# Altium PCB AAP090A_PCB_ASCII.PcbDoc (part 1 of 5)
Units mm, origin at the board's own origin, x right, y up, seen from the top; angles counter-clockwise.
Board outline 160 x 130 mm, 4 copper layers (Top Layer, Signal Layer 1, Signal Layer 2, Bottom Layer), stack 1.567 mm thick; 507 components, 275 nets, 1462 pads, 1041 vias.
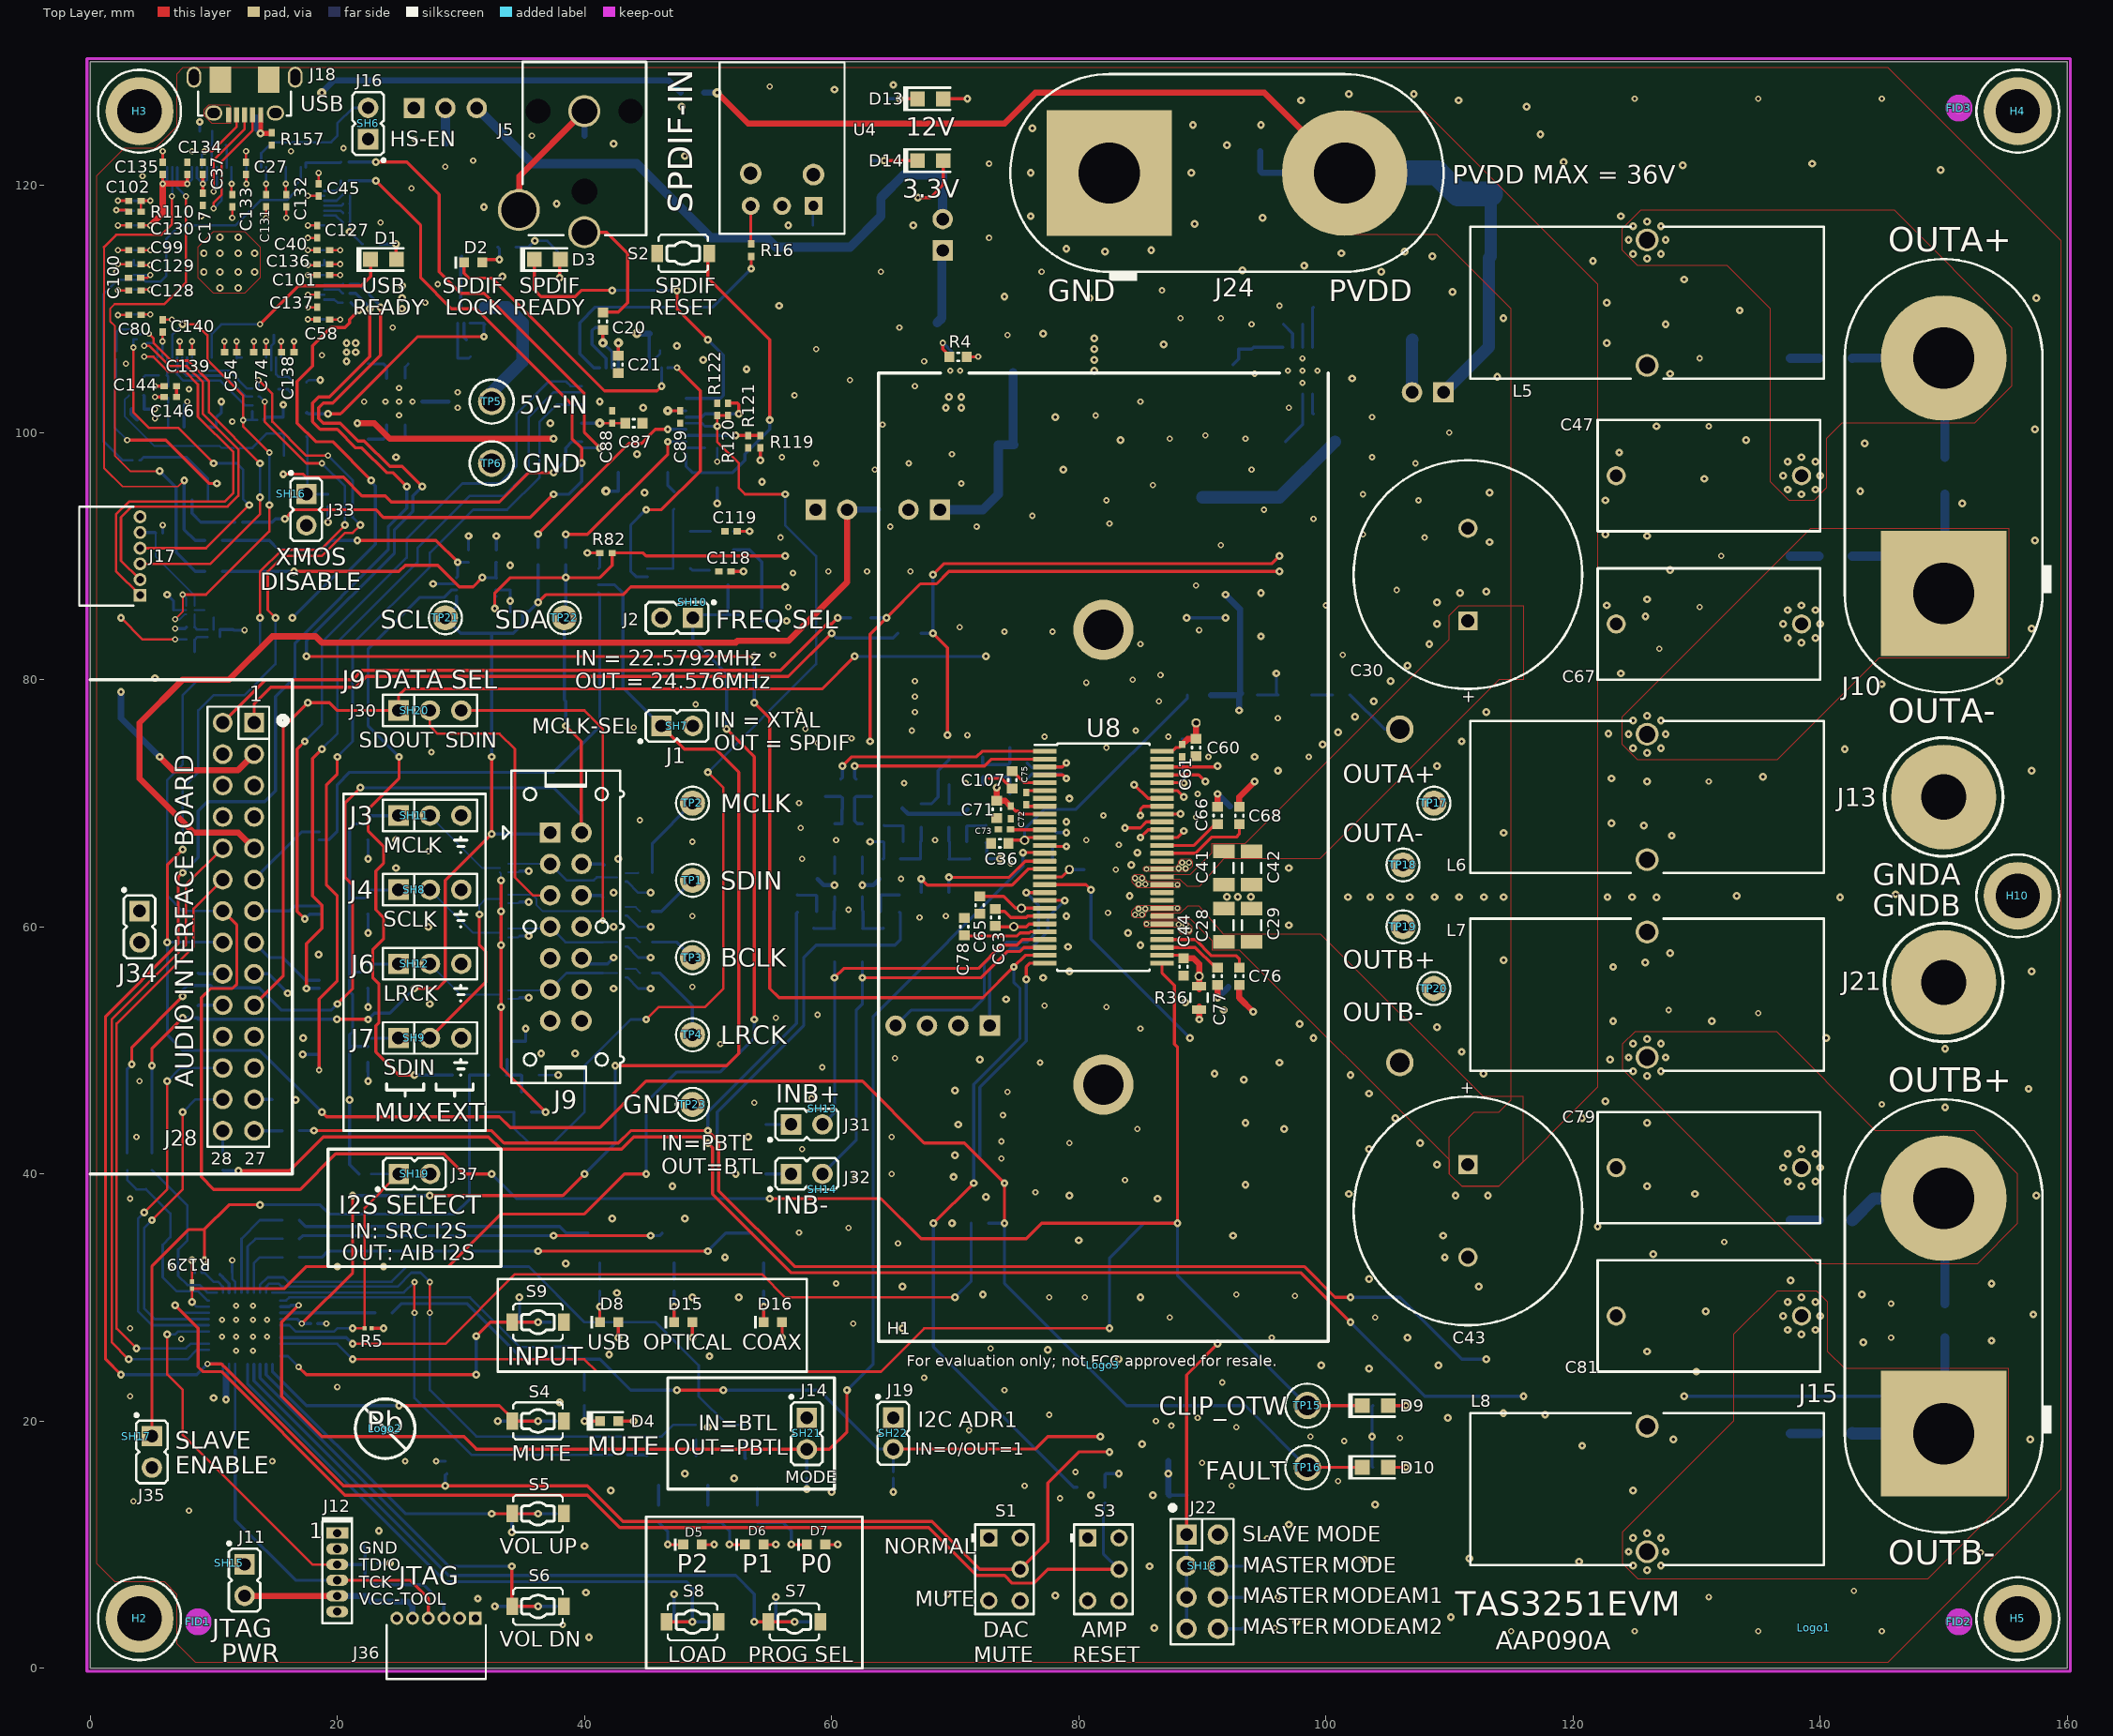
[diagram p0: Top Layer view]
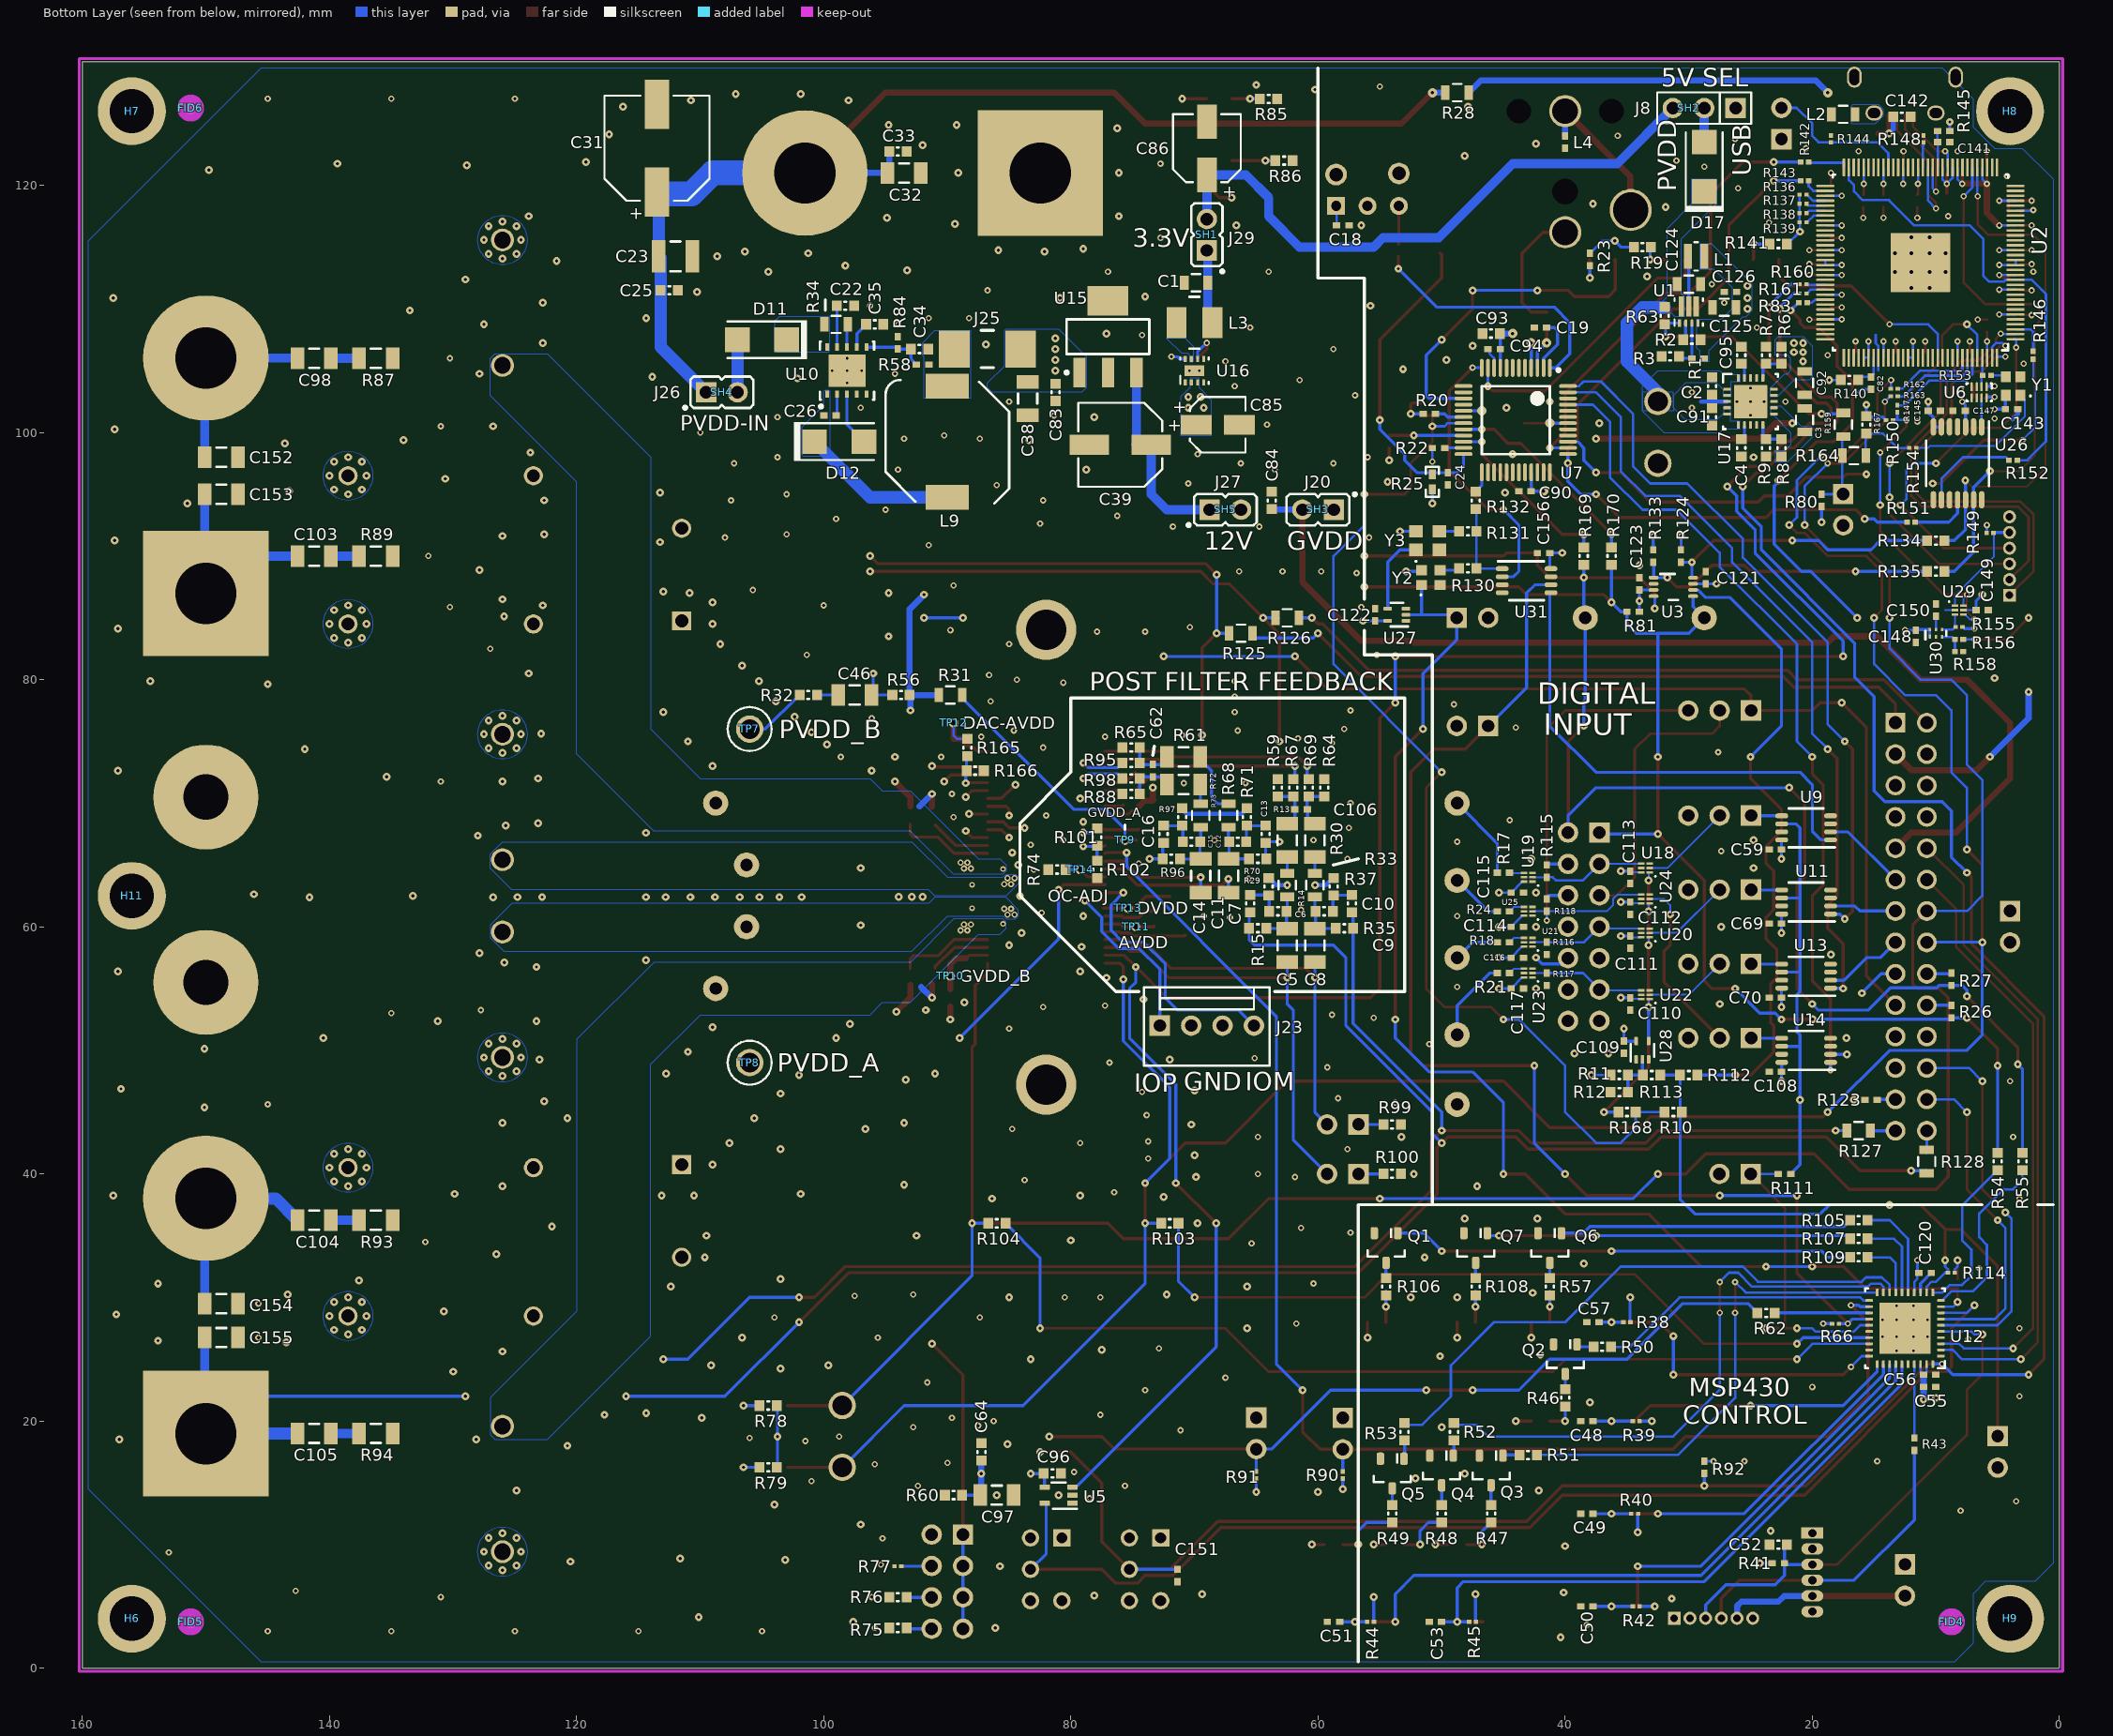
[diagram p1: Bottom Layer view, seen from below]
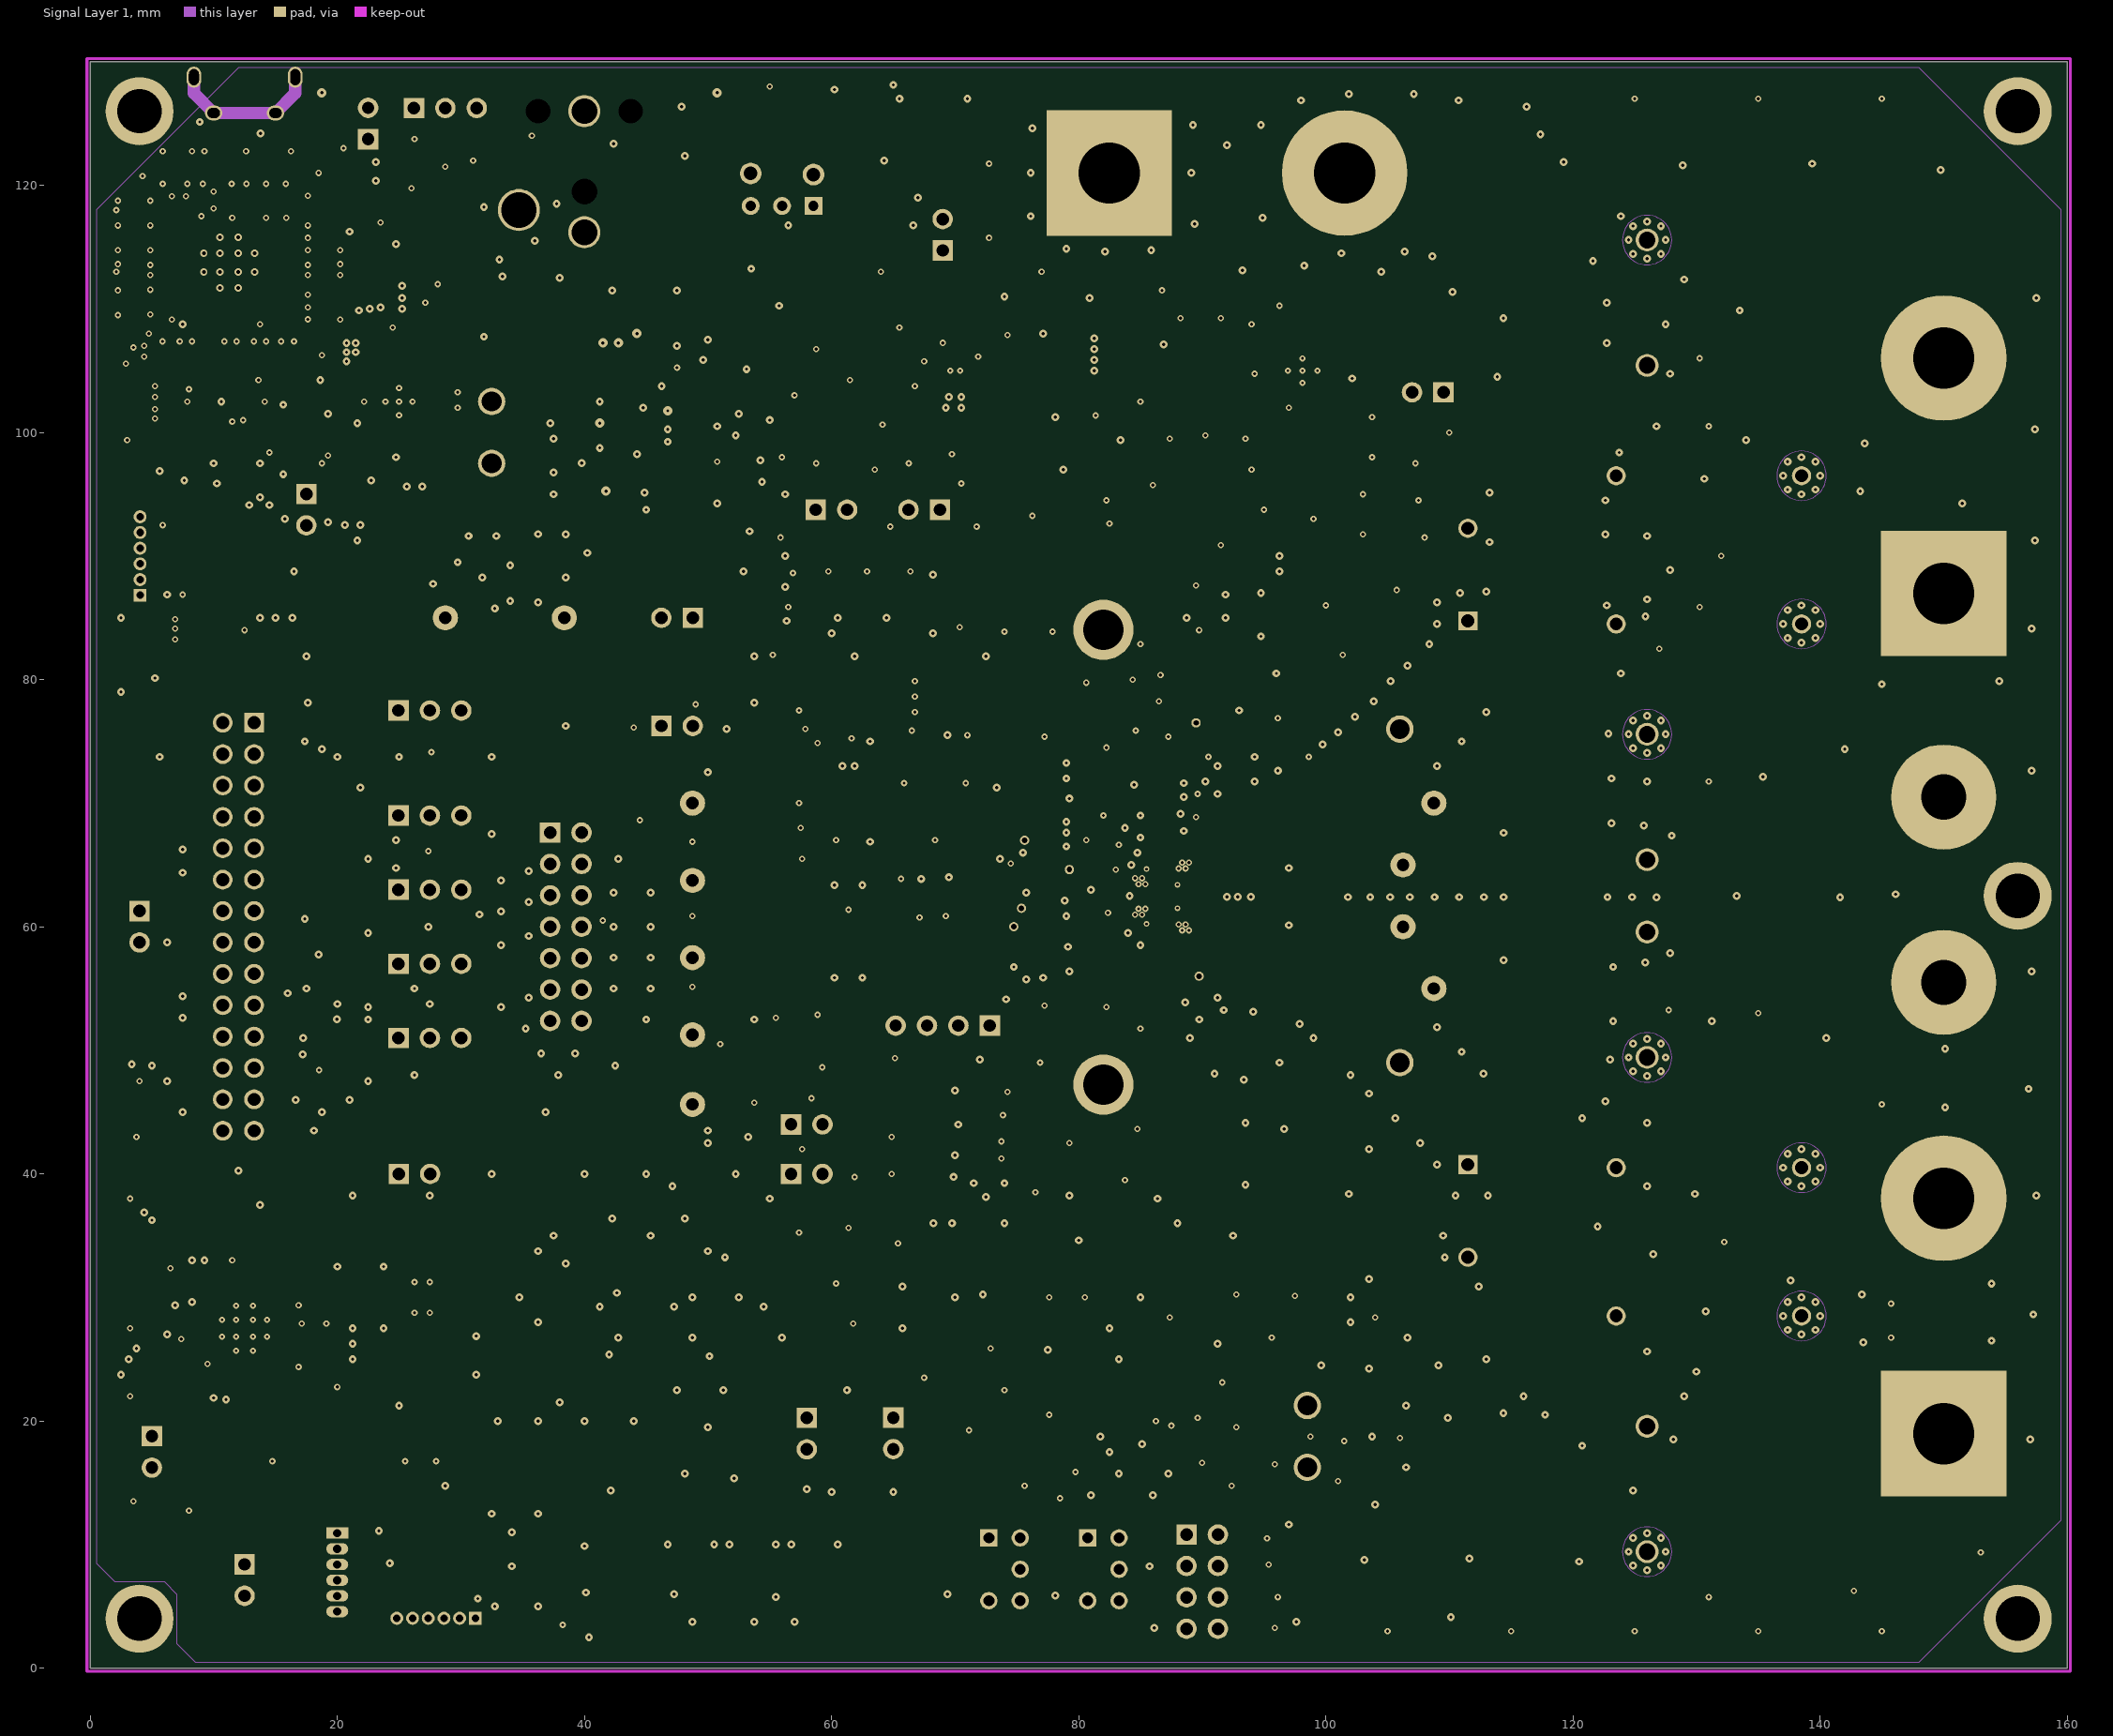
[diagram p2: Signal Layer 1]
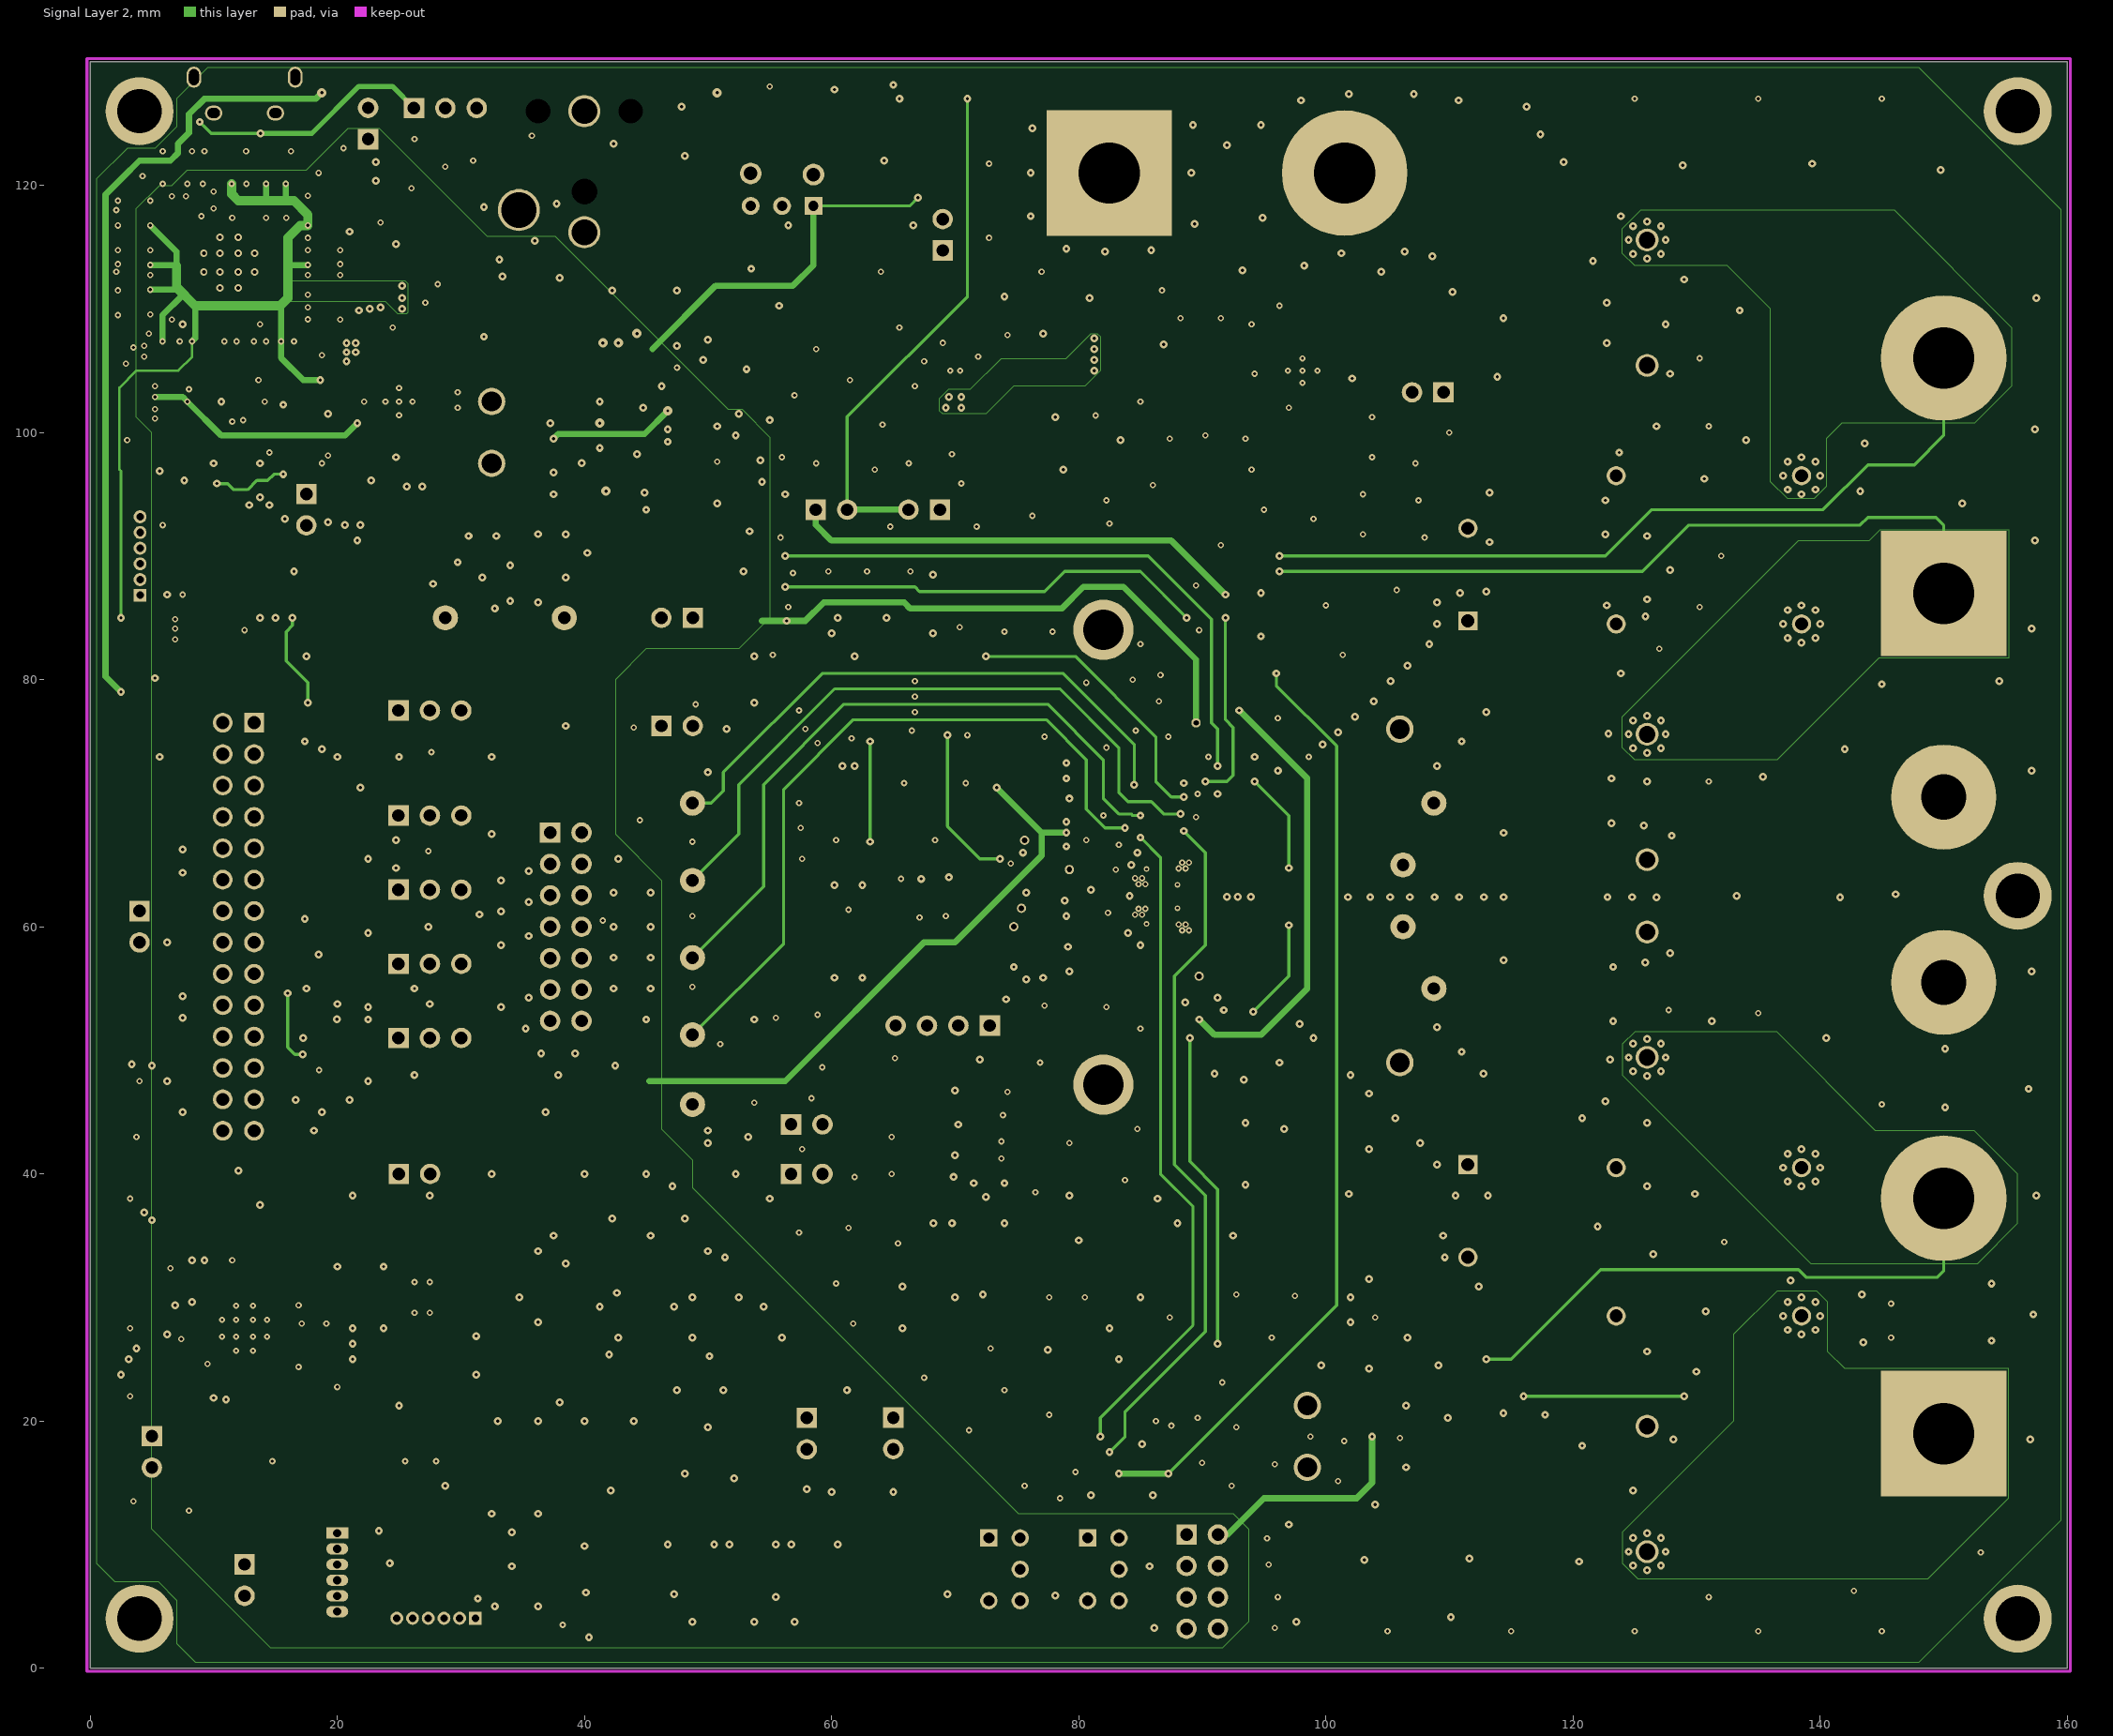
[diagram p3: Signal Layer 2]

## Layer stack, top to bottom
Top Solder: solder mask 0.0102, Solder Resist, Dk 3.5
Top Layer: signal copper 0.0696
Dielectric 1: prepreg 0.2032, FR-4, Dk 4.2
Signal Layer 1: signal copper 0.0356
Dielectric 2: core 0.9505, FR-4, Dk 4.2
Signal Layer 2: signal copper 0.0356
Dielectric 3: prepreg 0.2032, FR-4, Dk 4.2
Bottom Layer: signal copper 0.0696
Bottom Solder: solder mask 0.0102, Solder Resist, Dk 3.5

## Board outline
0,0 160,0 160,130 0,130

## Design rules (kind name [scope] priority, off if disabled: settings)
AcuteAngle [All] p0: scope1count=1 scope1_0_kind=Board scope1_0_value=Board scope2count=1 scope2_0_kind=Board scope2_0_value=Board commentlength=0 minimum=4.50000000000000E+0001
AcuteAngle [All] p1: minimum=4.50000000000000E+0001 checktracksonly=FALSE
AssemblyTestPointUsage [All] p0: scope1count=1 scope1_0_kind=Board scope1_0_value=Board scope2count=1 scope2_0_kind=Board scope2_0_value=Board commentlength=0
AssemblyTestPointUsage [All] p1: valid=2
AssemblyTestpoint [All] p0: scope1count=1 scope1_0_kind=Board scope1_0_value=Board scope2count=1 scope2_0_kind=Board scope2_0_value=Board commentlength=0
BoardOutlineClearance "BOC For Jacks at Edge" [All] p0: scope1count=1 scope1_0_kind=Component scope1_0_value=J18 scope2count=1 scope2_0_kind=Board scope2_0_value=Board commentlength=0 gap=0
BoardOutlineClearance [All] p0 off: scope1count=1 scope1_0_kind=Board scope1_0_value=Board scope2count=1 scope2_0_kind=Board scope2_0_value=Board commentlength=172 gap=0.5 // Protel DXP Scope 1 Expression Was: OnCopper and Not InComponentClass('Logo') and not InComponentClass('FiducialMark') and not InRegion(1000,500,4000,800) and not InPoly
BoardOutlineClearance BoardOutlineClearance_Poly [All] p0 off: scope1count=1 scope1_0_kind=Board scope1_0_value=Board scope2count=1 scope2_0_kind=Board scope2_0_value=Board commentlength=58 gap=0.5 // Protel DXP Scope 1 Expression Was: OnCopper and IsPoly
BoardOutlineClearance BoardOutlineClearance_MountingHoles [All] p0 off: scope1count=1 scope1_0_kind=Board scope1_0_value=Board scope2count=1 scope2_0_kind=Board scope2_0_value=Board commentlength=86 gap=0.25 // Protel DXP Scope 1 Expression Was: OnCopper and InComponentClass('Mounting Holes')
BoardOutlineClearance "BOC For Jacks at Edge" [InComponent('J18')] p1: gap=0 ignorepadtopadclearanceinfootprint=FALSE
BoardOutlineClearance BoardOutlineClearance_MountingHoles [OnCopper and InComponentClass('Mounting Holes')] p2: gap=0.25 ignorepadtopadclearanceinfootprint=FALSE
BoardOutlineClearance BoardOutlineClearance_Poly [OnCopper and IsPoly] p3: gap=0.5 ignorepadtopadclearanceinfootprint=FALSE
BoardOutlineClearance [OnCopper and Not InComponentClass('Logo') and not InComponentClass('FiducialMark') and not InRegion(1000,500,4000,800) and not InPoly] p4: gap=0.5 ignorepadtopadclearanceinfootprint=FALSE
Clearance [All] p0: scope1count=1 scope1_0_kind=Board scope1_0_value=Board scope2count=1 scope2_0_kind=Board scope2_0_value=Board commentlength=0 gap=0.2
Clearance Clearance_Poly [All] p0 off: scope1count=1 scope1_0_kind=Board scope1_0_value=Board scope2count=1 scope2_0_kind=Board scope2_0_value=Board commentlength=48 gap=0.2 // Protel DXP Scope 1 Expression Was: InPolygon
Clearance Clearance_Keepouts [All] p0 off: scope1count=1 scope1_0_kind=Board scope1_0_value=Board scope2count=1 scope2_0_kind=Board scope2_0_value=Board commentlength=99 gap=0 // Protel DXP Scope 2 Expression Was: ((IsTrack Or IsArc) And Not InPoly) And IsFree and IsKeepOut
Clearance "Clearance LibErrors" [All] p0 off: scope1count=1 scope1_0_kind=Board scope1_0_value=Board scope2count=1 scope2_0_kind=Board scope2_0_value=Board commentlength=83 gap=0.2 // Protel DXP Scope 1 Expression Was: HasFootprint('DSF*') or HasFootprint('RLT*')
Clearance "Fiducial Rules Error" [All] p0: scope1count=1 scope1_0_kind=Component scope1_0_value=FID* scope2count=1 scope2_0_kind=Board scope2_0_value=Board commentlength=0 gap=0.2
Clearance "Fiducial Rules Error" [InComponent('FID*')] p1: gap=0.2 ignorepadtopadclearanceinfootprint=TRUE except(0: Arc-SMDPad Arc-Hole Track-SMDPad Track-Hole SMDPad-Hole THPad-Hole Via-Hole Fill-Hole Poly-Hole Region-Hole Text-Hole)
Clearance "Clearance LibErrors" [HasFootprint('DSF*') or HasFootprint('RLT*')] p2: gap=0.2 ignorepadtopadclearanceinfootprint=FALSE except(0: Arc-Hole Track-Hole SMDPad-Hole THPad-Hole Via-Hole Fill-Hole Poly-Hole Region-Hole Text-Hole; 0.1: Track-SMDPad SMDPad-SMDPad)
Clearance Clearance_Keepouts [((IsTrack Or IsArc) And Not InPoly) And IsFree and IsKeepOut vs ((IsTrack Or IsArc) And Not InPoly) And IsFree and IsKeepOut] p3: gap=0 ignorepadtopadclearanceinfootprint=FALSE
Clearance Clearance_Poly [InPolygon] p4: gap=0.2 ignorepadtopadclearanceinfootprint=TRUE except(0: Arc-Hole Track-Hole SMDPad-Hole THPad-Hole Via-Hole Fill-Hole Poly-Hole Region-Hole Text-Hole)
Clearance [All] p5: gap=0.2 ignorepadtopadclearanceinfootprint=FALSE except(0: Arc-Hole Track-Hole SMDPad-Hole THPad-Hole Via-Hole Fill-Hole Poly-Hole Region-Hole Text-Hole)
ComponentClearance "CompClearance for Heatsink" [All] p0: scope1count=1 scope1_0_kind=Component scope1_0_value=H1 scope2count=1 scope2_0_kind=Board scope2_0_value=Board commentlength=0 gap=0 collisioncheckmode=3
ComponentClearance [All] p0: scope1count=1 scope1_0_kind=Board scope1_0_value=Board scope2count=1 scope2_0_kind=Board scope2_0_value=Board commentlength=0 gap=0.25 collisioncheckmode=3
ComponentClearance ComponentClearance_THtoTH [All] p0 off: scope1count=1 scope1_0_kind=Board scope1_0_value=Board scope2count=1 scope2_0_kind=Board scope2_0_value=Board commentlength=54 gap=0.25 collisioncheckmode=3 // Protel DXP Scope 2 Expression Was: IsThruComponent
ComponentClearance ComponentClearance_THtoSMT [All] p0 off: scope1count=1 scope1_0_kind=Board scope1_0_value=Board scope2count=1 scope2_0_kind=Board scope2_0_value=Board commentlength=53 gap=0.25 collisioncheckmode=3 // Protel DXP Scope 2 Expression Was: IsSMTComponent
ComponentClearance ComponentClearance_SmallPassives [All] p0 off: scope1count=1 scope1_0_kind=Board scope1_0_value=Board scope2count=1 scope2_0_kind=Board scope2_0_value=Board commentlength=653 gap=0.25 collisioncheckmode=3 // Protel DXP Scope 2 Expression Was: HasFootprint('0201*') or HasFootprint('0402*') or HasFootprint('0508') or HasFootprint('0603*') or HasFootprint('0612') or HasFootprint('0805*') or HasFootprint('0815*') or HasFootprint('0830*') or HasFootprint('1206*') or HasFootprint('1210*') or HasFootprint('1808*') or HasFootprint('1812*') or HasFootprint('1825*') or HasFootprint('2010*') or HasFootprint('2220*') or HasFootprint('2225*') or HasFootprint('2512*') or HasFootprint('2728*') or HasFootprint('3518*') or HasFootprint('DKQ*') or HasFootprint('OSC*') or HasFootprint('PFB*') or HasFootprint('RHB*') or HasFootprint('SOT*') or HasFootprint('XTAL*')
ComponentClearance ComponentClearance_MountingHoles [All] p0: scope1count=1 scope1_0_kind=ComponentClass scope1_0_value="Mounting Holes" scope2count=1 scope2_0_kind=Board scope2_0_value=Board commentlength=0 gap=0 collisioncheckmode=3
ComponentClearance ComponentClearance_Logo [All] p0: scope1count=1 scope1_0_kind=ComponentClass scope1_0_value=Logo scope2count=1 scope2_0_kind=Board scope2_0_value=Board commentlength=0 gap=0 collisioncheckmode=3
ComponentClearance ComponentClearance_Shunt [All] p0: scope1count=1 scope1_0_kind=ComponentClass scope1_0_value=Header scope2count=1 scope2_0_kind=ComponentClass scope2_0_value=Shunt commentlength=0 gap=0 collisioncheckmode=3
ComponentClearance ComponentClearance_MountingHoles_FiducialMarks [All] p0: scope1count=1 scope1_0_kind=ComponentClass scope1_0_value="Mounting Holes" scope2count=1 scope2_0_kind=ComponentClass scope2_0_value=FiducialMark commentlength=0 gap=0.25 collisioncheckmode=3
ComponentClearance "CompClearance for Heatsink" [InComponent('H1')] p1: gap=0 collisioncheckmode=3 verticalgap=0 showdistances=FALSE
ComponentClearance ComponentClearance_MountingHoles_FiducialMarks [InComponentClass('Mounting Holes') vs InComponentClass('FiducialMark')] p2: gap=0.25 collisioncheckmode=3 verticalgap=0 showdistances=FALSE
ComponentClearance ComponentClearance_Shunt [InComponentClass('Header') vs InComponentClass('Shunt')] p3: gap=0 collisioncheckmode=3 verticalgap=0 showdistances=FALSE
ComponentClearance ComponentClearance_Logo [InComponentClass('Logo')] p4: gap=0 collisioncheckmode=3 verticalgap=0 showdistances=FALSE
ComponentClearance ComponentClearance_MountingHoles [InComponentClass('Mounting Holes')] p5: gap=0 collisioncheckmode=3 verticalgap=0 showdistances=FALSE
ComponentClearance ComponentClearance_SmallPassives [HasFootprint('0201*') or HasFootprint('0402*') or HasFootprint('0508') or HasFootprint('0603*') or HasFootprint('0612') or HasFootprint('0805*') or HasFootprint('0815*') or HasFootprint('0830*') or HasFootprint('1206*') or HasFootprint('1210*') or HasFootprint('1808*') or HasFootprint('1812*') or HasFootprint('1825*') or HasFootprint('2010*') or HasFootprint('2220*') or HasFootprint('2225*') or HasFootprint('2512*') or HasFootprint('2728*') or HasFootprint('3518*') or HasFootprint('DKQ*') or HasFootprint('OSC*') or HasFootprint('PFB*') or HasFootprint('RHB*') or HasFootprint('SOT*') or HasFootprint('XTAL*') vs HasFootprint('0201*') or HasFootprint('0402*') or HasFootprint('0508') or HasFootprint('0603*') or HasFootprint('0612') or HasFootprint('0805*') or HasFootprint('0815*') or HasFootprint('0830*') or HasFootprint('1206*') or HasFootprint('1210*') or HasFootprint('1808*') or HasFootprint('1812*') or HasFootprint('1825*') or HasFootprint('2010*') or HasFootprint('2220*') or HasFootprint('2225*') or HasFootprint('2512*') or HasFootprint('2728*') or HasFootprint('3518*') or HasFootprint('DKQ*') or HasFootprint('OSC*') or HasFootprint('PFB*') or HasFootprint('RHB*') or HasFootprint('SOT*') or HasFootprint('XTAL*')] p6: gap=0.25 collisioncheckmode=3 verticalgap=0 showdistances=FALSE
ComponentClearance ComponentClearance_THtoSMT [IsThruComponent vs IsSMTComponent] p7: gap=0.25 collisioncheckmode=3 verticalgap=0 showdistances=FALSE
ComponentClearance ComponentClearance_THtoTH [IsThruComponent vs IsThruComponent] p8: gap=0.25 collisioncheckmode=3 verticalgap=0 showdistances=FALSE
ComponentClearance [All] p9: gap=0.25 collisioncheckmode=3 verticalgap=0 showdistances=FALSE
DiffPairsRouting [All] p0: scope1count=1 scope1_0_kind=Board scope1_0_value=Board scope2count=1 scope2_0_kind=Board scope2_0_value=Board commentlength=0
DiffPairsRouting [All] p1: maxlimit=2.54 minlimit=0.254 mostfreqgap=0.254 toplayer_minwidth=0.381 toplayer_maxwidth=0.381 toplayer_prefwidth=0.381 midlayer1_minwidth=0.381 midlayer1_maxwidth=0.381 midlayer1_prefwidth=0.381 midlayer2_minwidth=0.381 midlayer2_maxwidth=0.381 midlayer2_prefwidth=0.381 bottomlayer_minwidth=0.381 bottomlayer_maxwidth=0.381 bottomlayer_prefwidth=0.381 maxuncoupledlength=25.4
FabricationTestPointUsage TestPointUsage [All] p0: scope1count=1 scope1_0_kind=Board scope1_0_value=Board scope2count=1 scope2_0_kind=Board scope2_0_value=Board commentlength=0 valid=2 allowmultiple=FALSE
FabricationTestPointUsage TestPointUsage [All] p1: valid=2 allowmultiple=FALSE
FabricationTestpoint Testpoint [All] p0: scope1count=1 scope1_0_kind=Board scope1_0_value=Board scope2count=1 scope2_0_kind=Board scope2_0_value=Board commentlength=0 side=3 testpointundercomponent=TRUE minsize=1.016 maxsize=2.54 preferedsize=1.524 minholesize=0 maxholesize=1.016 preferedholesize=0.813 testpointgrid=0.025
FabricationTestpoint Testpoint [All] p1: side=3 testpointundercomponent=TRUE minsize=1.016 maxsize=2.54 preferedsize=1.524 minholesize=0 maxholesize=1.016 preferedholesize=0.813 testpointgrid=0.025 allowsidetop=TRUE allowsidebottom=TRUE usegrid=TRUE gridtolerance=0
FanoutControl Fanout_Small [All] p0 off: scope1count=1 scope1_0_kind=Board scope1_0_value=Board scope2count=1 scope2_0_kind=Board scope2_0_value=Board commentlength=84 // Protel DXP Scope 1 Expression Was: (CompPinCount < 5)   Fanout_Small (Default Rule)
FanoutControl Fanout_Default [All] p0: scope1count=1 scope1_0_kind=Board scope1_0_value=Board scope2count=1 scope2_0_kind=Board scope2_0_value=Board commentlength=30 // Fanout_Default (Default Rule)
FanoutControl Fanout_SOIC [All] p0 off: scope1count=1 scope1_0_kind=Board scope1_0_value=Board scope2count=1 scope2_0_kind=Board scope2_0_value=Board commentlength=71 // Protel DXP Scope 1 Expression Was: IsSOIC   Fanout_SOIC (Default Rule)
FanoutControl Fanout_BGA [All] p0 off: scope1count=1 scope1_0_kind=Board scope1_0_value=Board scope2count=1 scope2_0_kind=Board scope2_0_value=Board commentlength=69 // Protel DXP Scope 1 Expression Was: IsBGA   Fanout_BGA (Default Rule)
FanoutControl Fanout_LCC [All] p0 off: scope1count=1 scope1_0_kind=Board scope1_0_value=Board scope2count=1 scope2_0_kind=Board scope2_0_value=Board commentlength=69 // Protel DXP Scope 1 Expression Was: IsLCC   Fanout_LCC (Default Rule)
FanoutControl Fanout_LCC [IsLCC] p1: bgadir=Out bgaviamode=Centered fanoutstyle=Auto fanoutdirection=Alternating viagrid=0.025 // Fanout_LCC (Default Rule)
FanoutControl Fanout_BGA [IsBGA] p2: bgadir=Out bgaviamode=Centered fanoutstyle=Auto fanoutdirection=Alternating viagrid=0.025 // Fanout_BGA (Default Rule)
FanoutControl Fanout_Default [All] p4: bgadir=Out bgaviamode=Centered fanoutstyle=Auto fanoutdirection=Alternating viagrid=0.025 // Fanout_Default (Default Rule)
FanoutControl Fanout_Small [(CompPinCount < 5)] p5: bgadir=Out bgaviamode=Centered fanoutstyle=Auto fanoutdirection=OutThenIn viagrid=0.025 // Fanout_Small (Default Rule)
Height [All] p0: scope1count=1 scope1_0_kind=Board scope1_0_value=Board scope2count=1 scope2_0_kind=Board scope2_0_value=Board commentlength=0
Height [All] p1: minheight=0 maxheight=38.1 prefheight=12.7
HoleSize [All] p0: scope1count=1 scope1_0_kind=Board scope1_0_value=Board scope2count=1 scope2_0_kind=Board scope2_0_value=Board commentlength=0 absolutevalues=TRUE maxlimit=6.375 minlimit=0.2 maxpercent=80.000 minpercent=20.000
HoleSize [All] p1: absolutevalues=TRUE maxlimit=6.375 minlimit=0.2 maxpercent=80.000 minpercent=20.000
HoleToHoleClearance [All] p0: scope1count=1 scope1_0_kind=Board scope1_0_value=Board scope2count=1 scope2_0_kind=Board scope2_0_value=Board commentlength=0
LayerPairs [All] p0: scope1count=1 scope1_0_kind=Board scope1_0_value=Board scope2count=1 scope2_0_kind=Board scope2_0_value=Board commentlength=0 enforce=TRUE
MinimumAnnularRing [All] p0: scope1count=1 scope1_0_kind=Board scope1_0_value=Board scope2count=1 scope2_0_kind=Board scope2_0_value=Board commentlength=0 minimumring=0.127
MinimumAnnularRing MinimumAnnularRing_ThermalPadVias [All] p0 off: scope1count=1 scope1_0_kind=Board scope1_0_value=Board scope2count=1 scope2_0_kind=Board scope2_0_value=Board commentlength=63 minimumring=0.15 // Protel DXP Scope 1 Expression Was: IsVia and InAnyComponent
MinimumAnnularRing MinimumAnnularRing_ThermalPadVias [IsVia and InAnyComponent] p1: minimumring=0.15
MinimumAnnularRing [All] p2: minimumring=0.127
MinimumSolderMaskSliver "MinSolderMaskSliver LibErrors" [All] p0 off: scope1count=1 scope1_0_kind=Board scope1_0_value=Board scope2count=1 scope2_0_kind=Board scope2_0_value=Board commentlength=203 // Protel DXP Scope 1 Expression Was: HasFootprint('DCU*') or HasFootprint('DQM*') or HasFootprint('DRL*') or HasFootprint('DSF*') or HasFootprint('PFB*') or HasFootprint('PW*') or HasFootprint('TQFP*')
MinimumSolderMaskSliver [All] p0: scope1count=1 scope1_0_kind=Board scope1_0_value=Board scope2count=1 scope2_0_kind=Board scope2_0_value=Board commentlength=0
MinimumSolderMaskSliver MinimumSolderMaskSliver_Logo [All] p0: scope1count=1 scope1_0_kind=ComponentClass scope1_0_value=Logo scope2count=1 scope2_0_kind=ComponentClass scope2_0_value=Logo commentlength=0
MinimumSolderMaskSliver "MinSolderMaskSliver LibErrors" [HasFootprint('DCU*') or HasFootprint('DQM*') or HasFootprint('DRL*') or HasFootprint('DSF*') or HasFootprint('PFB*') or HasFootprint('PW*') or HasFootprint('TQFP*')] p1: minsoldermaskwidth=0.064
MinimumSolderMaskSliver MinimumSolderMaskSliver_Logo [InComponentClass('Logo') vs InComponentClass('Logo')] p2: minsoldermaskwidth=0.018
MinimumSolderMaskSliver [All] p3: minsoldermaskwidth=0.102
NetAntennae [All] p0: scope1count=1 scope1_0_kind=Board scope1_0_value=Board scope2count=1 scope2_0_kind=Board scope2_0_value=Board commentlength=0
PasteMaskExpansion [All] p0: scope1count=1 scope1_0_kind=Board scope1_0_value=Board scope2count=1 scope2_0_kind=Board scope2_0_value=Board commentlength=0 expansion=0
PlaneClearance [All] p0: scope1count=1 scope1_0_kind=Board scope1_0_value=Board scope2count=1 scope2_0_kind=Board scope2_0_value=Board commentlength=0 clearance=0.508
PlaneConnect [All] p0: scope1count=1 scope1_0_kind=Board scope1_0_value=Board scope2count=1 scope2_0_kind=Board scope2_0_value=Board commentlength=0 planeconnectstyle=Relief reliefexpansion=0.254 reliefentries=4 reliefconductorwidth=0.254 reliefairgap=0.254
PlaneConnect [All] p1: planeconnectstyle=Relief reliefexpansion=0.254 reliefentries=4 reliefconductorwidth=0.254 reliefairgap=0.254
PolygonConnect "GND Thermals 0.5mm" [All] p0 off: scope1count=1 scope1_0_kind=Board scope1_0_value=Board scope2count=1 scope2_0_kind=Net scope2_0_value=GND commentlength=416 connectstyle=Relief reliefconductorwidth=0.5 reliefentries=4 polygonreliefangle="90 Angle" // Protel DXP Scope 1 Expression Was: InComponent('C23') or InComponent('C30') or  InComponent('C32') or InComponent('C39') or  InComponent('C43') or InComponent('C47') or  InComponent('C67') or InComponent('C79') or  InComponent('C81') or InComponent('C85') or  InComponent('C86') or InComponent('L2') or  InComponent('R87') or InComponent('R89') or  InComponent('R93') or InComponent('R94') or  InComponent('U16')
PolygonConnect "PostFlood GND" [All] p0 off: scope1count=1 scope1_0_kind=Board scope1_0_value=Board scope2count=1 scope2_0_kind=Net scope2_0_value=GND commentlength=595 connectstyle=Direct reliefconductorwidth=0.254 reliefentries=4 polygonreliefangle="90 Angle" // Protel DXP Scope 1 Expression Was: InComponent('C16') or InComponent('C28') or InComponent('C29') or  InComponent('C31') or InComponent('C41') or InComponent('C42') or  InComponent('C44') or InComponent('C55') or InComponent('C56') or  InComponent('C60') or InComponent('C61') or InComponent('C63') or  InComponent('C65') or InComponent('C71') or InComponent('C72') or  InComponent('C73') or InComponent('C78') or InComponent('C124') or  InComponent('C125') or InComponent('C126')  or InComponent('J13') or InComponent('J21') or InComponent('J24') or InComponent('R74') or  InComponent('U1')
PolygonConnect "GND Thermals 0.25mm" [All] p0 off: scope1count=1 scope1_0_kind=Board scope1_0_value=Board scope2count=1 scope2_0_kind=Net scope2_0_value=GND commentlength=203 connectstyle=Relief reliefconductorwidth=0.25 reliefentries=4 polygonreliefangle="90 Angle" // Protel DXP Scope 1 Expression Was: InComponent('C*') or InComponent('D*') or InComponent('J*') or InComponent('Q*') or InComponent('R*') or InComponent('S*') or InComponent('U1') or InComponent('U4')
PolygonConnect PreFlood [All] p0: scope1count=1 scope1_0_kind=Board scope1_0_value=Board scope2count=1 scope2_0_kind=Board scope2_0_value=Board commentlength=0 connectstyle=Direct reliefconductorwidth=0.254 reliefentries=4 polygonreliefangle="90 Angle"
PolygonConnect "PostFlood GND" [InComponent('C16') or InComponent('C28') or InComponent('C29') or  InComponent('C31') or InComponent('C41') or InComponent('C42') or  InComponent('C44') or InComponent('C55') or InComponent('C56') or  InComponent('C60') or InComponent('C61') or InComponent('C63') or  InComponent('C65') or InComponent('C71') or InComponent('C72') or  InComponent('C73') or InComponent('C78') or InComponent('C124') or  InComponent('C125') or InComponent('C126')  or InComponent('J13') or InComponent('J21') or InComponent('J24') or InComponent('R74') or  InComponent('U1') vs InNet('GND')] p1: connectstyle=Direct reliefconductorwidth=0.254 reliefentries=4 polygonreliefangle="90 Angle" airgapwidth=0.254
PolygonConnect "GND Thermals 0.5mm" [InComponent('C23') or InComponent('C30') or  InComponent('C32') or InComponent('C39') or  InComponent('C43') or InComponent('C47') or  InComponent('C67') or InComponent('C79') or  InComponent('C81') or InComponent('C85') or  InComponent('C86') or InComponent('L2') or  InComponent('R87') or InComponent('R89') or  InComponent('R93') or InComponent('R94') or  InComponent('U16') vs InNet('GND')] p2: connectstyle=Relief reliefconductorwidth=0.5 reliefentries=4 polygonreliefangle="90 Angle" airgapwidth=0.2
PolygonConnect "GND Thermals 0.25mm" [InComponent('C*') or InComponent('D*') or InComponent('J*') or InComponent('Q*') or InComponent('R*') or InComponent('S*') or InComponent('U1') or InComponent('U4') vs InNet('GND')] p3: connectstyle=Relief reliefconductorwidth=0.25 reliefentries=4 polygonreliefangle="90 Angle" airgapwidth=0.2
PolygonConnect PreFlood [All] p4: connectstyle=Direct reliefconductorwidth=0.254 reliefentries=4 polygonreliefangle="90 Angle" airgapwidth=0.254
RoutingCorners [All] p0: scope1count=1 scope1_0_kind=Board scope1_0_value=Board scope2count=1 scope2_0_kind=Board scope2_0_value=Board commentlength=0 cornerstyle=45-Degree minsetback=2.54 maxsetback=2.54
RoutingLayers [All] p0: scope1count=1 scope1_0_kind=Board scope1_0_value=Board scope2count=1 scope2_0_kind=Board scope2_0_value=Board commentlength=0 top layer=Automatic mid layer 1=Automatic mid layer 2=Automatic bottom layer=Automatic
RoutingPriority [All] p0: scope1count=1 scope1_0_kind=Board scope1_0_value=Board scope2count=1 scope2_0_kind=Board scope2_0_value=Board commentlength=0
RoutingTopology [All] p0: scope1count=1 scope1_0_kind=Board scope1_0_value=Board scope2count=1 scope2_0_kind=Board scope2_0_value=Board commentlength=0 topology=Shortest
RoutingVias [All] p0: scope1count=1 scope1_0_kind=Board scope1_0_value=Board scope2count=1 scope2_0_kind=Board scope2_0_value=Board commentlength=0 holewidth=0.406 width=0.864 viastyle="Through Hole" minholewidth=0.2 minwidth=0.457 maxholewidth=1.016 maxwidth=1.651
RoutingVias ThermalPadVias [All] p0 off: scope1count=1 scope1_0_kind=Board scope1_0_value=Board scope2count=1 scope2_0_kind=Board scope2_0_value=Board commentlength=63 holewidth=0.2 width=0.5 viastyle="Through Hole" minholewidth=0.2 minwidth=0.5 maxholewidth=0.33 maxwidth=0.6 // Protel DXP Scope 1 Expression Was: IsVia and InAnyComponent
RoutingVias ThermalPadVias [IsVia and InAnyComponent] p1: holewidth=0.2 width=0.5 viastyle="Through Hole" minholewidth=0.2 minwidth=0.5 maxholewidth=0.33 maxwidth=0.6
RoutingVias [All] p2: holewidth=0.406 width=0.864 viastyle="Through Hole" minholewidth=0.2 minwidth=0.457 maxholewidth=1.016 maxwidth=1.651
ShortCircuit [All] p0: scope1count=1 scope1_0_kind=Board scope1_0_value=Board scope2count=1 scope2_0_kind=Board scope2_0_value=Board commentlength=0 allowed=FALSE
SilkToBoardRegionClearance [All] p0 off: scope1count=1 scope1_0_kind=Board scope1_0_value=Board scope2count=1 scope2_0_kind=Board scope2_0_value=Board commentlength=130 // Protel DXP Scope 1 Expression Was: Not ((IsComment or IsDesignator) And (Hide <> 'False')) and not InRegion(1000,500,4000,800)
SilkToBoardRegionClearance [Not ((IsComment or IsDesignator) And (Hide <> 'False')) and not InRegion(1000,500,4000,800)] p1:
SilkToSilkClearance [All] p0: scope1count=1 scope1_0_kind=Board scope1_0_value=Board scope2count=1 scope2_0_kind=Board scope2_0_value=Board commentlength=0
SilkToSilkClearance SilkToSilkClearance_Pb-FreeLogo [All] p0 off: scope1count=1 scope1_0_kind=Board scope1_0_value=Board scope2count=1 scope2_0_kind=Board scope2_0_value=Board commentlength=120 // Protel DXP Scope 2 Expression Was: (HasFootprint('Pb-Free_Overlay_Medium') OR HasFootprint('Pb-Free_Overlay_Small'))
SilkToSilkClearance SilkToSilkClearance_Pb-FreeLogo [(HasFootprint('Pb-Free_Overlay_Medium') OR HasFootprint('Pb-Free_Overlay_Small')) vs (HasFootprint('Pb-Free_Overlay_Medium') OR HasFootprint('Pb-Free_Overlay_Small'))] p1: silktosilkclearance=0
SilkToSilkClearance [All] p2: silktosilkclearance=0.102
SilkToSolderMaskClearance "Silk to Solder Mask Opening" [All] p0: scope1count=1 scope1_0_kind=Board scope1_0_value=Board scope2count=1 scope2_0_kind=Board scope2_0_value=Board commentlength=0
SilkToSolderMaskClearance SilkToComponentPadClearance [All] p0 off: scope1count=1 scope1_0_kind=Board scope1_0_value=Board scope2count=1 scope2_0_kind=Board scope2_0_value=Board commentlength=63 // Protel DXP Scope 1 Expression Was: IsPad and InAnycomponent
SilkToSolderMaskClearance SilkToComponentPadClearance [IsPad and InAnycomponent] p1: minsilkscreentomaskgap=0.127 clearancetoexposedcopper=TRUE
SilkToSolderMaskClearance "Silk to Solder Mask Opening" [All] p2: minsilkscreentomaskgap=0.102 clearancetoexposedcopper=FALSE
SolderMaskExpansion [All] p0: scope1count=1 scope1_0_kind=Board scope1_0_value=Board scope2count=1 scope2_0_kind=Board scope2_0_value=Board commentlength=0 expansion=0.05
SolderMaskExpansion [All] p1: expansion=0.05
UnRoutedNet [All] p0: scope1count=1 scope1_0_kind=Board scope1_0_value=Board scope2count=1 scope2_0_kind=Board scope2_0_value=Board commentlength=0
UnpouredPolygon [All] p0: scope1count=1 scope1_0_kind=Board scope1_0_value=Board scope2count=1 scope2_0_kind=Board scope2_0_value=Board commentlength=0
Width [All] p0: scope1count=1 scope1_0_kind=Board scope1_0_value=Board scope2count=1 scope2_0_kind=Board scope2_0_value=Board commentlength=0 maxlimit=2.54 minlimit=0.15 preferedwidth=0.254
Width [All] p1: maxlimit=2.54 minlimit=0.15 preferedwidth=0.254 toplayer_minwidth=0.152 midlayer1_minwidth=0.152 midlayer2_minwidth=0.152 minimp=50.000000 maximp=50.000000 favimp=50.000000 checkconnectedcopper=TRUE
14 further rules are at their usual default settings.

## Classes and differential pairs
component class "Mounting Holes": H2 H3 H4 H5 H6 H7 H8 H9 H10 H11 H12 H13 H14 H15
component class Header: J1 J2 J3 J4 J6 J7 J8 J11 J14 J16 J19 J20 J22 J26 J27 J29 J30 J31 J32 J33 J34 J35 J37
component class AAP090A_XMOS: C17 C27 C37 C40 C45 C54 C58 C74 C80 C82 C99 C100 C101 C102 C124 C125 C126 C127 C128 C129 C130 C131 C132 C133 C134 C135 C136 C137 C138 C139 C140 C141 C142 C143 C144 C145 C146 C147 C148 C149 C150 D1 J16 J17 J18 J33 L1 L2 R1 R2 R3 R63 R80 R81 R82 R83 R110 R124 R133 R134 R135 R136 R137 R138 R139 R140 R141 R142 R143 R144 R145 R146 R147 R148 R149 R150 R151 R152 R153 R154 R155 R156 R157 R158 R159 R160 R161 R162 R163 R164 R167 U1 U2 U3 U6 U26 U29 U30 Y1
component class AAP090A_TAS3251DKQ-IO: C5 C6 C7 C8 C9 C10 C11 C12 C13 C14 C15 C16 C28 C29 C30 C36 C41 C42 C43 C44 C47 C60 C61 C62 C63 C65 C66 C67 C68 C71 C72 C73 C75 C76 C77 C78 C79 C81 C98 C103 C104 C105 C106 C107 C152 C153 C154 C155 D9 D10 H1 J10 J13 J14 J15 J19 J20 J21 J22 J23 J31 J32 L5 L6 L7 L8 R13 R14 R15 R29 R30 R31 R33 R35 R36 R37 R59 R61 R64 R65 R67 R68 R69 R70 R71 R72 R73 R74 R75 R76 R77 R78 R79 R87 R88 R89 R90 R91 R93 R94 R95 R96 R97 R98 R99 R100 R101 R102 R125 R126 R127 R128 R165 R166 TP1 TP2 TP3 TP4 TP7 TP8 TP9 TP10 TP11 TP12 TP13 TP14 TP15 TP16 TP17 TP18 TP19 TP20 TP21 TP22 TP23 U8
component class AAP090A_SPDIF-SRC4392: C18 C19 C20 C21 C24 C59 C69 C70 C108 C110 C111 C112 C113 C114 C115 C116 C117 C118 C119 C120 C121 C122 C123 C156 D2 D3 J1 J3 J4 J5 J6 J7 J9 J28 J30 J34 L4 R11 R12 R16 R17 R18 R19 R20 R21 R22 R23 R24 R25 R26 R27 R28 R66 R115 R116 R117 R118 R119 R120 R121 R122 R123 R130 R131 R132 R168 R169 R170 S2 U4 U7 U9 U11 U13 U14 U18 U19 U20 U21 U22 U23 U24 U25 U27 U28 U31 Y2 Y3
component class AAP090A_PowerSupplies: C1 C2 C3 C4 C22 C23 C25 C26 C31 C32 C33 C34 C35 C38 C39 C83 C84 C85 C86 C87 C88 C89 C90 C91 C92 C93 C94 C95 D11 D12 D13 D14 D17 J8 J24 J25 J26 J27 J29 L3 L9 R4 R6 R7 R8 R9 R34 R58 R84 R85 R86 TP5 TP6 U10 U15 U16 U17
component class AAP090A_MSP430: C46 C48 C49 C50 C51 C52 C53 C55 C56 C57 C64 C96 C97 C109 C151 D4 D5 D6 D7 D8 D15 D16 J2 J11 J12 J35 J36 J37 Q1 Q2 Q3 Q4 Q5 Q6 Q7 R5 R10 R32 R38 R39 R40 R41 R42 R43 R44 R45 R46 R47 R48 R49 R50 R51 R52 R53 R54 R55 R56 R57 R60 R62 R92 R103 R104 R105 R106 R107 R108 R109 R111 R112 R113 R114 R129 S1 S3 S4 S5 S6 S7 S8 S9 U5 U12
component class AssemblyNote: ZZ1 ZZ2 ZZ3
component class FiducialMark: FID1 FID2 FID3 FID4 FID5 FID6
component class AAP090A_EVM_Hardware: FID1 FID2 FID3 FID4 FID5 FID6 H2 H3 H4 H5 H6 H7 H8 H9 H10 H11 Logo1 Logo2 Logo3 SH1 SH2 SH3 SH4 SH5 SH6 SH7 SH8 SH9 SH10 SH11 SH12 SH13 SH14 SH15 SH16 SH17 SH18 SH19 SH20 SH21 SH22 ZZ1 ZZ2 ZZ3
component class Logo: Logo1
component class Shunt: SH1 SH2 SH3 SH4 SH5 SH6 SH7 SH8 SH9 SH10 SH11 SH12 SH13 SH14 SH15 SH16 SH17 SH18 SH19 SH20 SH21 SH22

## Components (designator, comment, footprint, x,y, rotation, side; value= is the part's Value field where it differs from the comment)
C1 "GRM21BZ71A226ME15L" 0805_KTR 69.875,112.125 r0 bottom
C2 "GRM188R61A106ME69D" 0603L 28.125,103.75 r270 bottom
C3 "GRM21BZ71A226ME15L" 0805_KTR 20.625,101 r90 bottom
C4 "GRM188R71C105KA12D" 0603L 25.75,98.75 r90 bottom
C5 "GRM31CR71C106KAC7L" 1206_180L 62.5,58.5 r270 bottom
C6 "DNP" 0603L 63.25,61.25 r0 bottom
C7 "DNP" 0603L 65.5,61.875 r90 bottom
C8 "GRM31CR71C106KAC7L" 1206_180L 60.25,58.5 r270 bottom
C9 "DNP" 0603L 59.5,61.25 r180 bottom
C10 "DNP" 0603L 57.25,61.875 r90 bottom
C11 "GRM31CR71C106KAC7L" 1206_180L 67.25,64.125 r270 bottom
C12 "DNP" 0603L 66.5,66.875 r180 bottom
C13 "DNP" 0603L 64.25,67.5 r90 bottom
C14 "GRM31CR71C106KAC7L" 1206_180L 69.5,64.125 r270 bottom
C15 "DNP" 0603L 70.25,66.875 r0 bottom
C16 "DNP" 0603L 72.5,67.5 r90 bottom
C17 "GRM155R71C104KA88D" 0402L 9.125,118.875 r90 top
C18 "GRM155R71A104KA01D" 0402L 58,116.75 r180 bottom
C19 "GRM155R71A104KA01D" 0402L 42,108.5 r180 bottom
C20 "GRM188R71C104KA01D" 0603L 41.5,109 r90 top
C21 "GRM188R71C104KA01D" 0603L 42.75,105.5 r270 top
C22 "C0603C104K5RACTU" 0603L 98.25,110.25 r180 bottom
C23 "C1210C225K1RACTU" 1210_210L 112,114.25 r180 bottom
C24 "GRM155R71C104KA88D" 0402L 49.5,96.25 r90 bottom
C25 "GRM188R72A104KA35J" 0603L 112.5,111.5 r180 bottom
C26 "GRM155R71E473KA88D" 0402L 99.5,101.375 r0 bottom
C27 "GRM155R71C104KA88D" 0402L 12.625,121.375 r270 top
C28 "GRM31CR72A105KA01L" 1206_180L 91.75,60.125 r270 top
C29 "GRM31CR72A105KA01L" 1206_180L 94,60.125 r270 top
C30 "+" FC_1800x3550 111.5,88.5 r90 top locked
C31 "+" SM_RADIAL_F 113.5,123 r90 bottom
C32 "GRM31CR72A105KA01L" 1206_180L 93.5,121 r0 bottom
C33 "06031C103KAT2A" 0603L 94,122.75 r180 bottom
C34 "GRM188R71H562KA01D" 0603L 92.25,106.75 r0 bottom
C35 "C0603X472K5RACTU" 0603L 95.875,108.75 r180 bottom
C36 "C0603C104K5RACTU" 0603L 73.625,66.75 r180 top
C37 "GRM155R71C104KA88D" 0402L 9.125,121.375 r270 top
C38 "GRM31CR71E475KA88L" 1206_180L 83.5,102.75 r270 bottom
C39 "+" SM_RADIAL_D 76,99 r0 bottom
C40 "GRM155R71C104KA88D" 0402L 18.875,114.75 r180 top
C41 "GRM31CR72A105KA01L" 1206_180L 91.75,64.75 r90 top
C42 "GRM31CR72A105KA01L" 1206_180L 94,64.75 r90 top
C43 "+" FC_1800x3550 111.5,37 r270 top locked
C44 "C0603C104K5RACTU" 0603L 88.5,56.75 r270 top
C45 "GRM155R71C104KA88D" 0402L 18.5,119.625 r270 top
C46 "GRM31CR72A105KA01L" 1206_180L 97.5,78.75 r0 bottom
C47 "B32652A3684J" B32652_1800x900x1750 131,96.5 r180 top locked
C48 "GRM1555C1E471JA01D" 0402L 38.25,20 r0 bottom
C49 "GRM1555C1E471JA01D" 0402L 38.25,12.5 r0 bottom
C50 "GRM1555C1E471JA01D" 0402L 38.25,5 r0 bottom
C51 "GRM1555C1E471JA01D" 0402L 58.75,3.75 r0 bottom
C52 "885012206036" 0603L 22.75,10 r180 bottom
C53 "GRM1555C1E471JA01D" 0402L 50.5,3.75 r0 bottom
C54 "GRM155R71C104KA88D" 0402L 11.375,106.5 r0 top
C55 "GRM152R60J105ME15D" 0402L 10.5,22.75 r0 bottom
C56 "GRM155R71A104KA01D" 0402L 10.5,23.75 r0 bottom
C57 "GRM1555C1E471JA01D" 0402L 37.75,28 r0 bottom
C58 "GRM155R71C104KA88D" 0402L 18.875,109.125 r180 top
C59 "GRM155R71A104KA01D" 0402L 23,66.25 r180 bottom
C60 "GRM188R61A106ME69D" 0603L 89.5,74.5 r270 top
C61 "GRM155R71A104KA01D" 0402L 88.375,74.25 r270 top
C62 "GRM1555C1H102JA01D" 0402L 73.375,72.625 r270 bottom
C63 "GRM188R71C105KA12D" 0603L 73.25,60.75 r270 top
C64 "C0603C104K5RACTU" 0603L 87.25,17.5 r90 bottom
C65 "GRM188R71C105KA12D" 0603L 72,61.75 r90 top
C66 "GRM188R71E333KA01D" 0603L 91.25,69 r270 top
C67 "B32652A3684J" B32652_1800x900x1750 131,84.5 r180 top locked
C68 "GRM188R71E333KA01D" 0603L 93,69 r270 top
C69 "GRM155R71A104KA01D" 0402L 23,60.25 r180 bottom
C70 "GRM155R71A104KA01D" 0402L 23,54.25 r180 bottom
C71 "GRM188R61A106ME69D" 0603L 73.375,69.5 r270 top
C72 "GRM155R71A104KA01D" 0402L 74.5,69.25 r270 top
C73 "GRM155R71A104KA01D" 0402L 74,67.875 r180 top
C74 "GRM155R71C104KA88D" 0402L 13.75,106.5 r0 top
C75 "C1005X5R1A225K050BC" 0402L 75.75,70.375 r270 top
C76 "GRM188R71E333KA01D" 0603L 93,56 r90 top
C77 "GRM188R71E333KA01D" 0603L 91.25,56 r90 top
C78 "GRM188R71H473KA61D" 0603L 70.75,60 r90 top
C79 "B32652A3684J" B32652_1800x900x1750 131,40.5 r180 top locked
C80 "GRM155R71C104KA88D" 0402L 3.625,109.5 r0 top
C81 "B32652A3684J" B32652_1800x900x1750 131,28.5 r180 top locked
C82 "" 0402L 15.25,104 r270 bottom
C83 "GRM188R71E474KA12D" 0603L 81.25,103.25 r270 bottom
C84 "C0603C104K5RACTU" 0603L 63.75,94.5 r270 bottom
C85 "+" SM_RADIAL_B 68.125,100.625 r180 bottom
C86 "+" SM_RADIAL_C 69,123 r90 bottom
C87 "GRM188R61A106ME69D" 0603L 44,100.75 r0 top
C88 "GRM155R71A104KA01D" 0402L 42.25,101.25 r270 top
C89 "GRM155R71A104KA01D" 0402L 47.75,101.25 r90 top
C90 "GRM155R71A104KA01D" 0402L 43.25,95.25 r180 bottom
C91 "GRM188R61A106ME69D" 0603L 28.125,101.25 r90 bottom
C92 "GRM21BZ71A226ME15L" 0805_KTR 20.625,104 r270 bottom
C93 "GRM188R61A106ME69D" 0603L 46,108 r0 bottom
C94 "GRM155R71A104KA01D" 0402L 45.75,106.75 r180 bottom
C95 "GRM188R71C105KA12D" 0603L 25.75,106.25 r270 bottom
C96 "C0603C104K5RACTU" 0603L 81.5,15.75 r180 bottom
C97 "GRM31CR72A105KA01L" 1206_180L 86,14 r0 bottom
C98 "DNP" 1206_180L 141.25,106 r0 bottom
C99 "GRM155R71C104KA88D" 0402L 3.625,114.75 r0 top
C100 "GRM155R71C104KA88D" 0402L 3.6,112.5 r0 top
C101 "GRM155R71C104KA88D" 0402L 18.875,112.75 r180 top
C102 "GRM155R71C104KA88D" 0402L 3.625,118.75 r0 top
C103 "DNP" 1206_180L 141.25,90 r0 bottom
C104 "DNP" 1206_180L 141.25,36.25 r0 bottom
C105 "DNP" 1206_180L 141.25,19 r0 bottom
C106 "GRM1555C1H102JA01D" 0402L 61.375,69.5 r180 bottom
C107 "GRM188R71C105KA12D" 0603L 74.625,71.875 r90 top
C108 "GRM155R71A104KA01D" 0402L 23,48.25 r180 bottom
C109 "GRM155R71A104KA01D" 0402L 35.25,50.25 r90 bottom
C110 "GRM155R71A104KA01D" 0402L 34.75,53.75 r90 bottom
C111 "GRM155R71A104KA01D" 0402L 34.75,58.75 r90 bottom
C112 "GRM155R71A104KA01D" 0402L 34.75,61.5 r90 bottom
C113 "GRM155R71A104KA01D" 0402L 34.75,64 r90 bottom
C114 "GRM155R71A104KA01D" 0402L 43.875,60 r0 bottom
C115 "GRM155R71A104KA01D" 0402L 43.875,62.75 r0 bottom
C116 "GRM155R71A104KA01D" 0402L 43.875,57.5 r0 bottom
C117 "GRM155R71A104KA01D" 0402L 43.875,55 r0 bottom
C118 "GRM155R71A104KA01D" 0402L 51.375,88.75 r0 top
C119 "GRM155R71A104KA01D" 0402L 51.875,92 r0 top
C120 "GRM155R71A104KA01D" 0402L 10.875,32 r0 bottom
C121 "GRM155R71A104KA01D" 0402L 28.625,88.25 r270 bottom
C122 "GRM155R71A104KA01D" 0402L 55.375,85.25 r270 bottom
C123 "GRM155R71A104KA01D" 0402L 34,87.75 r270 bottom
C124 "GRM21BZ71A226ME15L" 0805_KTR 30,112 r180 bottom
C125 "GRM21BZ71A226ME15L" 0805_KTR 27.125,110.125 r0 bottom
C126 "GRM155R71C104KA88D" 0402L 26.625,111.375 r0 bottom
C127 "GRM155R71C104KA88D" 0402L 18.375,116.25 r90 top
C128 "GRM155R71C104KA88D" 0402L 3.625,111.5 r0 top
C129 "GRM155R71C104KA88D" 0402L 3.625,113.625 r0 top
C130 "GRM155R71C104KA88D" 0402L 3.625,116.75 r0 top
C131 "GRM155R71C104KA88D" 0402L 14.25,118.75 r90 top
C132 "GRM155R71C104KA88D" 0402L 15.875,118.75 r90 top
C133 "GRM155R71C104KA88D" 0402L 11.5,118.75 r90 top
C134 "GRM155R71C104KA88D" 0402L 7.875,121.375 r270 top
C135 "GRM155R71C104KA88D" 0402L 5.875,121.375 r270 top
C136 "GRM155R71C104KA88D" 0402L 18.875,113.625 r180 top
C137 "GRM155R71C104KA88D" 0402L 18.375,110.625 r90 top
C138 "GRM155R71C104KA88D" 0402L 16,106.5 r180 top
C139 "GRM155R71C104KA88D" 0402L 7.75,106.5 r0 top
C140 "GRM155R71C104KA88D" 0402L 5.875,108.625 r270 top
C141 "GRM155R71C104KA88D" 0402L 9.375,123.5 r180 bottom
C142 "GRM188R71A225KE15D" 0603L 12.75,125.55 r0 bottom
C143 "GRM155R71C104KA88D" 0402L 3.875,101.875 r0 bottom
C144 "GRM155R71C104KA88D" 0402L 6.5,103.75 r180 top
C145 "GRM155R71C104KA88D" 0402L 10.125,101.75 r0 bottom
C146 "GRM155R71C104KA88D" 0402L 6.5,102.875 r180 top
C147 "GRM155R71C104KA88D" 0402L 8.125,101.75 r180 bottom
C148 "GRM155R71C104KA88D" 0402L 11.625,83.5 r90 bottom
C149 "GRM155R71C104KA88D" 0402L 6.25,85.625 r0 bottom
C150 "GRM1555C1E471JA01D" 0402L 10,85.625 r270 bottom
C151 "GRM155R71A104KA01D" 0402L 71.375,7.5 r90 bottom
C152 "DNP" 1206L 148.75,98 r0 bottom
C153 "DNP" 1206L 148.75,95 r0 bottom
C154 "DNP" 1206L 148.75,29.5 r0 bottom
C155 "DNP" 1206L 148.75,26.75 r0 bottom
C156 "GRM155R71A104KA01D" 0402L 41.75,90.25 r180 bottom
D1 "USB RDY" LTST-C170TBKT_Blue 23.75,114 r180 top
D2 "SPDIF-LOCK" "LB Q39G_BLUE" 31,113.75 r180 top
D3 "SPDIF-READY" LED_LTST-C171 37,114 r180 top
D4 "MUTE" LED_LTST-C190_Red 42,20 r180 top
D5 "P2" "LB Q39G_BLUE" 48.75,10 r180 top
D6 "P1" "LB Q39G_BLUE" 53.75,10 r180 top
D7 "P0" "LB Q39G_BLUE" 58.75,10 r180 top
D8 "USB" "LB Q39G_BLUE" 42,28 r180 top
D9 "CLIP_OTW" LTST-C170KFKT_Orange 104,21.25 r180 top
D10 "FAULT" LED_LTST-C170_Red 104,16.25 r180 top
D11 "SK310A-TP" SMA 105,107.5 r0 bottom
D12 "B1100-13-F" SMA 98.75,99.25 r180 bottom
D13 "12V" LED_LTST-C171 68,127 r180 top
D14 "3.3V" LED_LTST-C171 68,122 r180 top
D15 "OPTICAL" "LB Q39G_BLUE" 48,28 r180 top
D16 "COAX" "LB Q39G_BLUE" 55.25,28 r180 top
D17 "B1100-13-F" SMA 28.75,121.5 r90 bottom
FID1 "Fiducial" Fiducial10-20 8.75,3.75 r0 top
FID2 "Fiducial" Fiducial10-20 151.25,3.75 r0 top
FID3 "Fiducial" Fiducial10-20 151.25,126.25 r0 top
FID4 "Fiducial" Fiducial10-20 8.75,3.75 r180 bottom
FID5 "Fiducial" Fiducial10-20 151.25,3.75 r180 bottom
FID6 "Fiducial" Fiducial10-20 151.25,126.25 r180 bottom
H1 "ATS078036036-TI1OP-1099-C1-R1" Advanced_ATS078036036-TI1OP-1099-C1-R1 82,65.625 r90 top locked
H2 "M3x8mm" "APM_RM3X8MM 2701" 4,4 r0 top
H3 "M3x8mm" "APM_RM3X8MM 2701" 4,126 r0 top locked
H4 "M3x8mm" "APM_RM3X8MM 2701" 156,126 r0 top
H5 "M3x8mm" "APM_RM3X8MM 2701" 156,4 r0 top
H6 "M3x25mm" Keystone24438 156,4 r180 bottom
H7 "M3x25mm" Keystone24438 156,126 r180 bottom
H8 "M3x25mm" Keystone24438 4,126 r180 bottom
H9 "M3x25mm" Keystone24438 4,4 r180 bottom
H10 "M3x8mm" "APM_RM3X8MM 2701" 156,62.5 r0 top
H11 "M3x25mm" Keystone24438 156,62.5 r180 bottom
J1 "MCLK-SEL" Sullins_PBC02SAAN 47.5,76.25 r90 top
J2 "FREQ SEL" Sullins_PBC02SAAN 47.5,85 r270 top
J3 "" PBC03SAAN 27.5,69 r0 top
J4 "" PBC03SAAN 27.5,63 r0 top
J5 "SPDIF-IN" Keystone_971 40,126 r270 top locked
J6 "" PBC03SAAN 27.5,57 r0 top
J7 "" PBC03SAAN 27.5,51 r0 top
J8 "5V SEL" PBC03SAAN 28.75,126.25 r0 bottom
J9 "I2X" CONN_SBH11-PBPC-D07-ST-BK 38.5,60 r270 top locked
J10 "OUTA" Pomona_6883 150,96.5 r90 top locked
J11 "JTAG POWER" Sullins_PBC02SAAN 12.5,7.125 r0 top
J12 "JTAG" Mill-Max_851-XX-006-10-001000 20,7.75 r90 top
J13 "GNDA" Keystone_7007 150,70.5 r0 top locked
J14 "MODE" Sullins_PBC02SAAN 58,18.98 r0 top
J15 "OUTB" Pomona_6883 150,28.5 r90 top locked
J16 "HS-EN" Sullins_PBC02SAAN 22.5,125 r180 top
J17 "JTAG" SULLINS_LPPB061NGCN-RC 1.5,90 r270 top
J18 "USB" CONN_USB_DX4R205JJA 12.5,130 r180 top locked
J19 "ADR" Sullins_PBC02SAAN 65,19 r0 top
J20 "GVDD" Sullins_PBC02SAAN 60,93.75 r270 bottom
J21 "GNDB" Keystone_7007 150,55.5 r0 top locked
J22 "PEC04DAAN" CONN_PEC04DAAN 90,7 r270 top
J23 "0022112042" CONN_22112042 69,52 r180 bottom locked
J24 "PVDD" Pomona_6883 92,121 r0 top locked
J25 "S1911-46R" HARWIN_S1911-46R 86.75,106.75 r180 bottom
J26 "PVDD-IN" Sullins_PBC02SAAN 108.25,103.25 r90 bottom
J27 "12V" Sullins_PBC02SAAN 67.5,93.75 r90 bottom
J28 "SSW-114-01-G-D" CONN_SSW-114-01-G-D 12,60 r90 top locked
J29 "3.3V" Sullins_PBC02SAAN 69,116 r0 bottom
J30 "J9 DATA SEL" PBC03SAAN 27.5,77.5 r0 top
J31 "INB+" Sullins_PBC02SAAN 58,44 r90 top
J32 "INB-" Sullins_PBC02SAAN 58,40 r90 top
J33 "" Sullins_PBC02SAAN 17.5,93.75 r0 top locked
J34 "PBC02SAAN" Sullins_PBC02SAAN 4,60 r0 top
J35 "SLAVE ENABLE" Sullins_PBC02SAAN 5,17.5 r0 top
J36 "JTAG-RA" SULLINS_LPPB061NGCN-RC 28,1.5 r0 top
J37 "I2S SELECT" Sullins_PBC02SAAN 26.25,40 r90 top
L1 "VLS2012ET-R47N" VLS2012ET 29.4,114.25 r180 bottom
L2 "MPZ2012S601A" 0805_KTR 17.5,125.75 r0 bottom
L3 "VLCF4020T-2R2N1R7" VLCF4020 70,108.875 r180 bottom
L4 "MMZ1005Y121C" 0402L 40,123.5 r270 bottom
L5 "MA5173" MA5173 126,110.5 r90 top locked
L6 "MA5173" MA5173 126,70.5 r90 top locked
L7 "MA5173" MA5173 126,54.5 r270 top locked
L8 "MA5173" MA5173 126,14.5 r270 top locked
L9 "7447714101" WE-PD_1050 90,99.25 r90 bottom
Logo1 "Texas Instruments" TI_Stacked_Overlay_Small 139.5,3.25 r0 top
Logo2 "Pb-Free Symbol" Pb-Free_Overlay_Medium 23.875,19.375 r0 top
Logo3 "FCC disclaimer" FCC_disclaimer 82,24.5 r0 top
Q1 "MMBT2222A" SOT-23 54.5,34 r270 bottom
Q2 "MMBT2222A" SOT-23 40,25 r270 bottom
Q3 "MMBT2222A" SOT-23 46,16 r270 bottom
Q4 "MMBT2222A" SOT-23 50,16 r270 bottom
Q5 "MMBT2222A" SOT-23 54,15.75 r270 bottom
Q6 "MMBT2222A" SOT-23 41.25,34 r270 bottom
Q7 "MMBT2222A" SOT-23 47.25,34 r270 bottom
R1 "ERJ-2RKF4022X" 0402L 29.25,106 r180 bottom
R2 "RC0603FR-071ML" 0603L 29.75,107.5 r180 bottom
R3 "RC0603FR-07162KL" 0603L 31.5,106.15 r180 bottom
R4 "RC0603FR-07100KL" 0603L 70.25,106.125 r0 top
R5 "RC0201FR-0710KL" 0201L 22.5,27.5 r0 top
R6 "RC0603FR-0733K2L" 0603L 22.5,106.25 r270 bottom
R7 "RC0603FR-0710K7L" 0603L 23.75,106.25 r270 bottom
R8 "RC0603FR-0713K7L" 0603L 22.5,98.75 r90 bottom
R9 "RC0603FR-0711KL" 0603L 23.75,98.75 r90 bottom
R10 "DNP" 0603L 31.25,45 r180 bottom
R11 "DNP" 0603L 35.625,48 r0 bottom
R12 "DNP" 0603L 35.625,46.625 r180 bottom
R13 "RC1206JR-070RL" 1206L 62.5,67 r270 bottom
R14 "" 0805_KTR 62.5,63.375 r270 bottom
R15 "DNP" 0603L 64.875,59.875 r180 bottom
R16 "ERJ-2RKF33R0X" 0402L 53.5,114.75 r270 top
R17 "RC0402FR-0749R9L" 0402L 45,64.375 r0 bottom
R18 "RC0402FR-0749R9L" 0402L 45,58.75 r0 bottom
R19 "RC0603JR-07560RL" 0603L 33.75,115 r180 bottom
R20 "RC0402FR-071KL" 0402L 51,101.5 r180 bottom
R21 "RC0402FR-0749R9L" 0402L 45,56.25 r0 bottom
R22 "RC0402FR-074K99L" 0402L 50.25,98.75 r180 bottom
R23 "RC0402FR-071KL" 0402L 38,114 r90 bottom
R24 "RC0402FR-0749R9L" 0402L 45,61.25 r0 bottom
R25 "" 0402 50.75,96 r90 bottom
R26 "ERJ-2GE0R00X" 0402L 8.75,53.125 r270 bottom
R27 "ERJ-2GE0R00X" 0402L 8.75,55.75 r270 bottom
R28 "DNP" 0805_KTR 48.75,127.5 r0 bottom
R29 "DNP" 0603L 64,63.25 r270 bottom
R30 "RC1206JR-070RL" 1206L 60.25,67 r270 bottom
R31 "RC0805JR-070RL" 0805_KTR 89.75,78.75 r180 bottom
R32 "RC0603FR-07100KL" 0603L 101.25,78.75 r0 bottom
R33 "" 0805_KTR 60.25,63.375 r270 bottom
R34 "ERJ-6ENF1823V" 0805_KTR 99,108.75 r180 bottom
R35 "DNP" 0603L 57.875,59.875 r0 bottom
R36 "RC0805JR-070RL" 0805_KTR 89.75,54.25 r90 top
R37 "DNP" 0603L 58.75,63.25 r270 bottom
R38 "RC0201FR-0725K5L" 0201L 35,28 r0 bottom
R39 "RC0201FR-0725K5L" 0201L 34.25,20 r0 bottom
R40 "RC0201FR-0725K5L" 0201L 34.375,12.5 r0 bottom
R41 "RC0402FR-0747KL" 0402L 22.75,8.5 r0 bottom
R42 "RC0201FR-0725K5L" 0201L 34.25,5 r0 bottom
R43 "RC0402FR-0749R9L" 0402L 11.75,18.125 r270 bottom
R44 "RC0201FR-0725K5L" 0201L 55.75,3.75 r0 bottom
R45 "RC0201FR-0725K5L" 0201L 47.5,3.75 r0 bottom
R46 "RC0603JR-07560RL" 0603L 40,21.875 r90 bottom
R47 "RC0603JR-07560RL" 0603L 46,12.5 r90 bottom
R48 "RC0603JR-07560RL" 0603L 50,12.5 r90 bottom
R49 "RC0603JR-07560RL" 0603L 54,12.5 r90 bottom
R50 "RC0603FR-072KL" 0603L 37,26 r180 bottom
R51 "RC0603FR-072KL" 0603L 43,17.25 r180 bottom
R52 "RC0603FR-072KL" 0603L 49,19.125 r90 bottom
R53 "RC0603FR-072KL" 0603L 53,19.125 r90 bottom
R54 "ERJ-3GEY0R00V" 0603L 5,41 r270 bottom
R55 "ERJ-3GEY0R00V" 0603L 3,41 r270 bottom
R56 "RC0603FR-078K06L" 0603L 93.75,78.75 r180 bottom
R57 "RC0603JR-07560RL" 0603L 41.25,30.875 r90 bottom
R58 "RC0402FR-074K99L" 0402L 92,105.5 r180 bottom
R59 "RC0603FR-07100KL" 0603L 63.25,71.25 r270 bottom
R60 "RC0603FR-073K3L" 0603L 89.5,14 r180 bottom
R61 "RC1206JR-070RL" 1206L 70.875,73.75 r180 bottom
R62 "ERJ-3GEY0R00V" 0603L 23.75,28.75 r180 bottom
R63 "DNP" 0603L 31.95,109.45 r270 bottom
R64 "RC0603FR-07100KL" 0603L 59.5,71.25 r270 bottom
R65 "RC0603FR-07100KL" 0603L 75.125,74.5 r180 bottom
R66 "RC0201FR-0710KL" 0201L 18.125,27.875 r0 bottom
R67 "RC0603FR-07499RL" 0603L 62,71.25 r270 bottom
R68 "" 0805_KTR 67.25,69 r270 bottom
R69 "RC0603FR-07499RL" 0603L 60.75,71.25 r270 bottom
R70 "DNP" 0603L 64.875,65.5 r0 bottom
R71 "DNP" 0603L 65.75,68.875 r270 bottom
R72 "RC1206JR-070RL" 1206L 70.875,71.5 r180 bottom
R73 "" 0805_KTR 69.5,69 r270 bottom
R74 "RC0603FR-0722KL" 0603L 81.125,64.625 r180 bottom
R75 "RC0603FR-0730KL" 0603L 94,3.25 r180 bottom
R76 "RC0603FR-0720KL" 0603L 94,5.75 r180 bottom
R77 "RC0201FR-0710KL" 0201L 94,8.25 r180 bottom
R78 "RC0603JR-07560RL" 0603L 104.5,21.25 r180 bottom
R79 "RC0603JR-07560RL" 0603L 104.5,16.25 r180 bottom
R80 "ERJ-2RKF1002X" 0402L 19.25,94.5 r90 bottom
R81 "RC0402FR-074K99L" 0402L 34.5,85.5 r180 bottom
R82 "RC0402FR-074K99L" 0402L 41.75,90.25 r180 top
R83 "RC0201FR-0733R2L" 0201 20.75,110.5 r180 bottom
R84 "RC0402FR-071KL" 0402L 94,107.25 r270 bottom
R85 "RC0603FR-071K5L" 0603L 64,127 r180 bottom
R86 "RC0603FR-07499RL" 0603L 62.75,122 r180 bottom
R87 "DNP" 1206L 136.25,106 r0 bottom
R88 "RC0603FR-07100KL" 0603L 75.125,70.75 r180 bottom
R89 "DNP" 1206L 136.25,90 r0 bottom
R90 "RC0201FR-0710KL" 0201L 58,15.625 r90 bottom
R91 "RC0201FR-0710KL" 0201L 65,15.625 r90 bottom
R92 "ERJ-2RKF1002X" 0402L 28.75,16.25 r270 bottom
R93 "DNP" 1206L 136.25,36.25 r0 bottom
R94 "DNP" 1206L 136.25,19 r0 bottom
R95 "RC0603FR-07499RL" 0603L 75.125,73.25 r180 bottom
R96 "DNP" 0603L 71.875,65.5 r180 bottom
R97 "DNP" 0603L 71,68.875 r270 bottom
R98 "RC0603FR-07499RL" 0603L 75.125,72 r180 bottom
R99 "ERJ-3GEY0R00V" 0603L 54,44 r0 bottom
R100 "ERJ-3GEY0R00V" 0603L 54,40 r0 bottom
R101 "DNP" 0603L 77.875,67.25 r270 bottom
R102 "ERJ-3GEY0R00V" 0603L 77.875,64.625 r90 bottom
R103 "ERJ-3GEY0R00V" 0603L 72,36 r0 bottom
R104 "ERJ-3GEY0R00V" 0603L 86,36 r0 bottom
R105 "RC0603FR-072KL" 0603L 16.25,36.25 r180 bottom
R106 "RC0603JR-07560RL" 0603L 54.5,30.875 r90 bottom
R107 "RC0603FR-072KL" 0603L 16.25,34.75 r180 bottom
R108 "RC0603JR-07560RL" 0603L 47.25,30.875 r90 bottom
R109 "RC0603FR-072KL" 0603L 16.25,33.25 r180 bottom
R110 "RC0402FR-071KL" 0402L 3.625,117.875 r180 top
R111 "ERJ-2GE0R00X" 0402L 22.25,40 r180 bottom
R112 "ERJ-3GEY0R00V" 0603L 30,48 r0 bottom
R113 "ERJ-3GEY0R00V" 0603L 33,48 r180 bottom
R114 "RC0201FR-0710KL" 0201L 8.75,32 r180 bottom
R115 "RC0402FR-07100KL" 0402L 41.5,64.5 r270 bottom
R116 "RC0402FR-07100KL" 0402L 41.5,58.25 r90 bottom
R117 "RC0402FR-07100KL" 0402L 41.5,55.75 r90 bottom
R118 "RC0402FR-07100KL" 0402L 41.5,61.75 r270 bottom
R119 "DNP" 0402L 54.25,99.25 r270 top
R120 "DNP" 0402L 51.625,101.875 r90 top
R121 "ERJ-2RKF1002X" 0402L 53.25,99.25 r270 top
R122 "DNP" 0402L 50.75,101.875 r90 top
R123 "RMCF0402FT10K0" 0402L 15.25,46 r0 bottom
R124 "RC0402FR-074K99L" 0402L 30.625,90 r90 bottom
R125 "RC0805JR-070RL" 0805_KTR 66.25,83.75 r180 bottom
R126 "RC0805JR-070RL" 0805_KTR 62.5,85 r180 bottom
R127 "RC0805JR-070RL" 0805_KTR 16.25,43.5 r180 bottom
R128 "RC0805JR-070RL" 0805_KTR 10.75,41 r90 bottom
R129 "RC0201FR-0710KL" 0201L 8.25,31 r90 top
R130 "ERJ-3GEY0R00V" 0603L 47.875,89 r180 bottom
R131 "ERJ-3GEY0R00V" 0603L 47.875,92 r180 bottom
R132 "ERJ-3GEY0R00V" 0603L 47.25,94.5 r90 bottom
R133 "RC0402FR-074K99L" 0402L 32.875,90 r90 bottom
R134 "ERJ-3GEY0R00V" 0603L 10,91.25 r0 bottom
R135 "ERJ-3GEY0R00V" 0603L 10,88.75 r0 bottom
R136 "RC0201FR-0747KL" 0201L 20.75,119.25 r0 bottom
R137 "RC0201FR-0747KL" 0201L 20.75,118.5 r0 bottom
R138 "RC0201FR-0747KL" 0201L 20.75,117.75 r0 bottom
R139 "RC0201FR-0747KL" 0201L 20.75,117 r0 bottom
R140 "RC0603FR-074R75L" 0603L 17,104.25 r180 bottom
R141 "RC0603JR-07560RL" 0603L 22.75,115.25 r0 bottom
R142 "RC0201FR-0733R2L" 0201 20.625,121.875 r180 bottom
R143 "RC0201FR-0733R2L" 0201 20.625,120.375 r180 bottom
R144 "RC0201FR-0710KL" 0201L 18.5,123.75 r270 bottom
R145 "ERJ-2RKF1002X" 0402L 9.375,124.375 r180 bottom
R146 "RC0201FR-0733R2L" 0201 2.125,106.25 r90 bottom
R147 "ERJ-1GE0R00C" 0201L 13.125,101.92 r270 bottom
R148 "RC0201FR-0743R2L" 0201L 11,123.75 r270 bottom
R149 "RC0201FR-0710KL" 0201L 5.625,91.875 r180 bottom
R150 "RC0201FR-0710KL" 0201L 13.75,101 r180 bottom
R151 "RC0201FR-0733R2L" 0201 12,92.75 r180 bottom
R152 "RC0201FR-0733R2L" 0201 3.75,97.75 r0 bottom
R153 "RC0201FR-0733R2L" 0201 5.875,104.625 r0 bottom
R154 "RC0201FR-0710KL" 0201L 11.875,98.75 r180 bottom
R155 "RC0201FR-0710KL" 0201L 8.125,84.25 r0 bottom
R156 "RC0201FR-0725K5L" 0201 8.125,83.25 r0 bottom
R157 "RC0402FR-0747KL" 0402L 14.7,123.75 r90 top
R158 "RC0201FR-0751KL" 0201 8.125,82.25 r180 bottom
